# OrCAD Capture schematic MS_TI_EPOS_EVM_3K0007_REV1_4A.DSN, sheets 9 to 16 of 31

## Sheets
9 Pg08: Ethernet RMII: size C
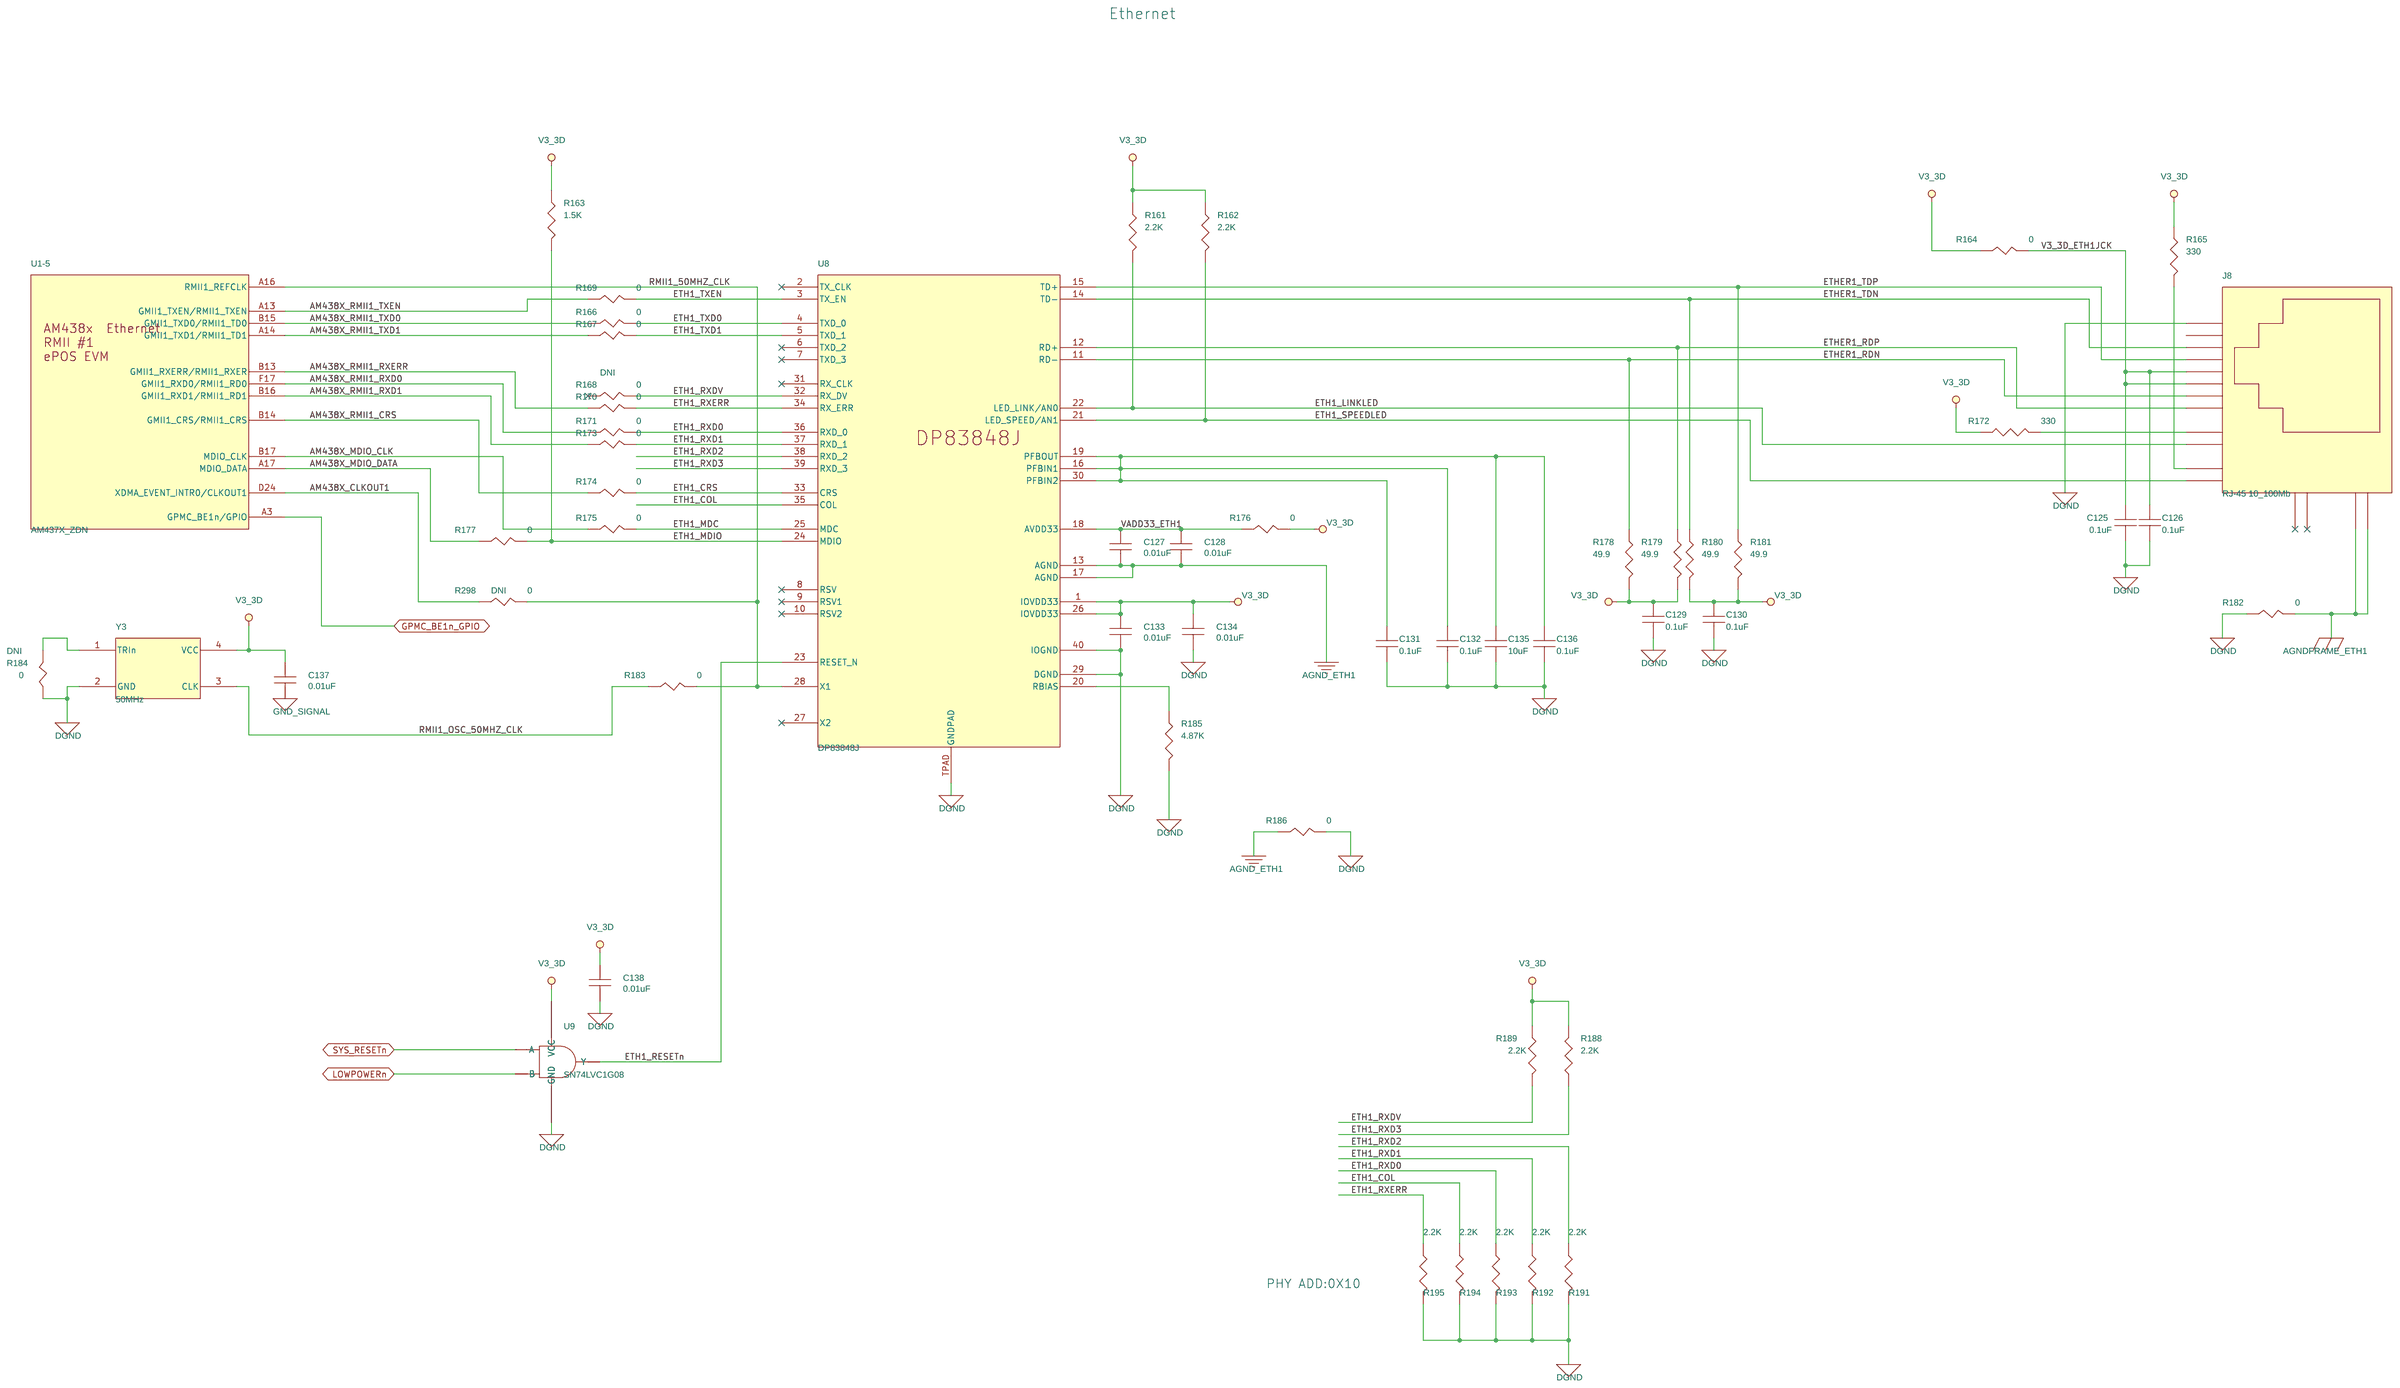
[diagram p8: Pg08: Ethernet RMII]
10 Pg19: USB Port #0: size C
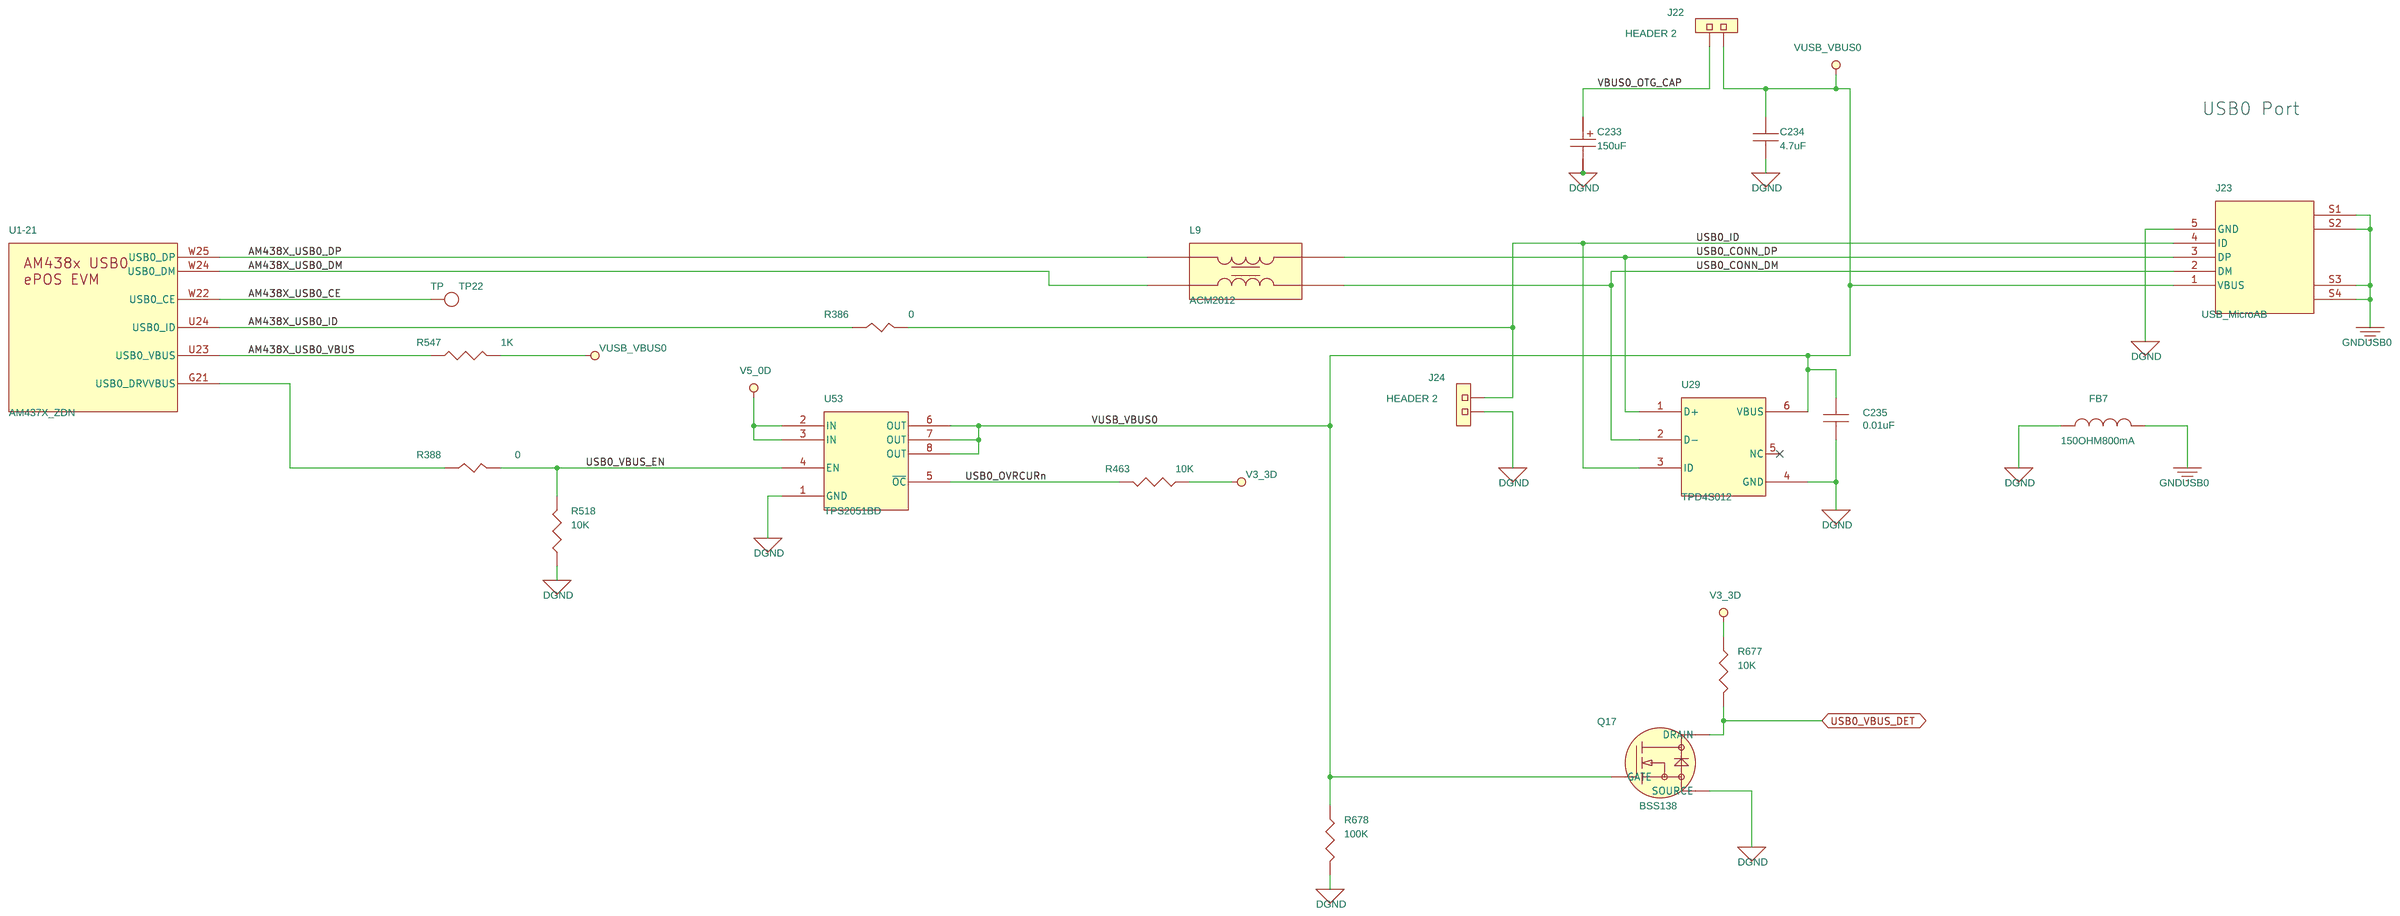
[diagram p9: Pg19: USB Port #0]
11 Pg10: JTAG Debug: size C
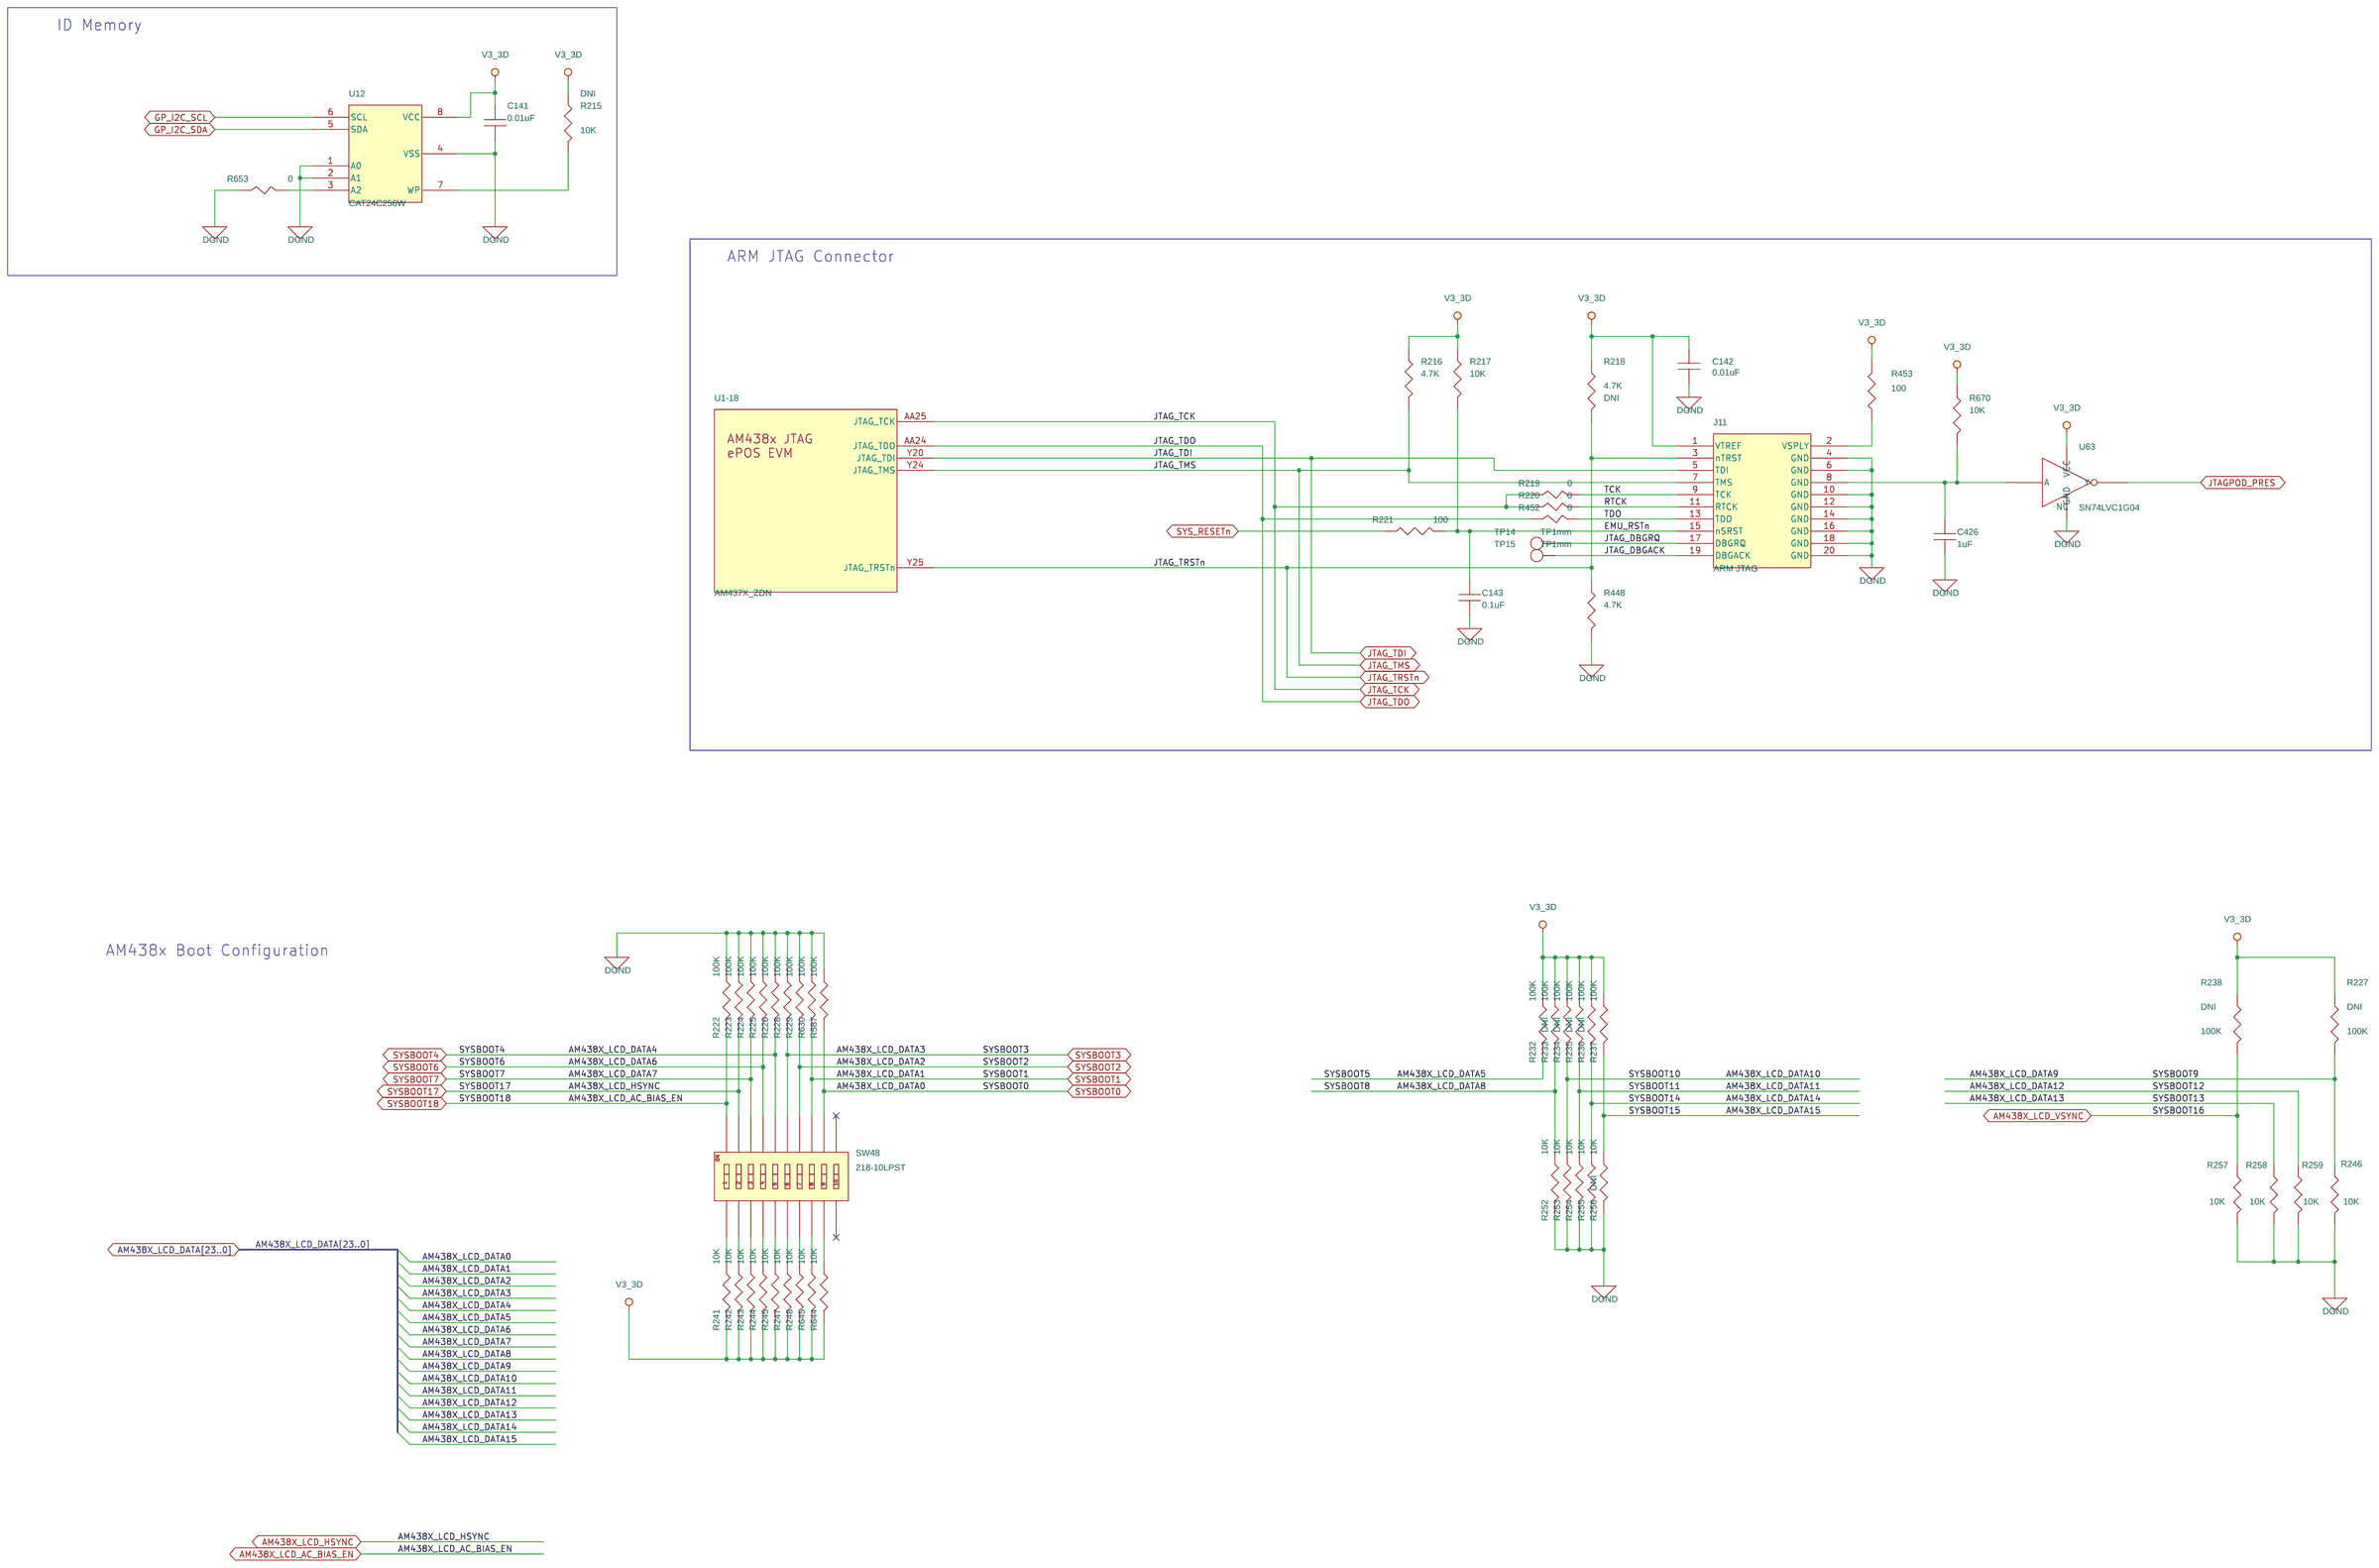
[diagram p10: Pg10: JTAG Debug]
12 Pg01: Title Page
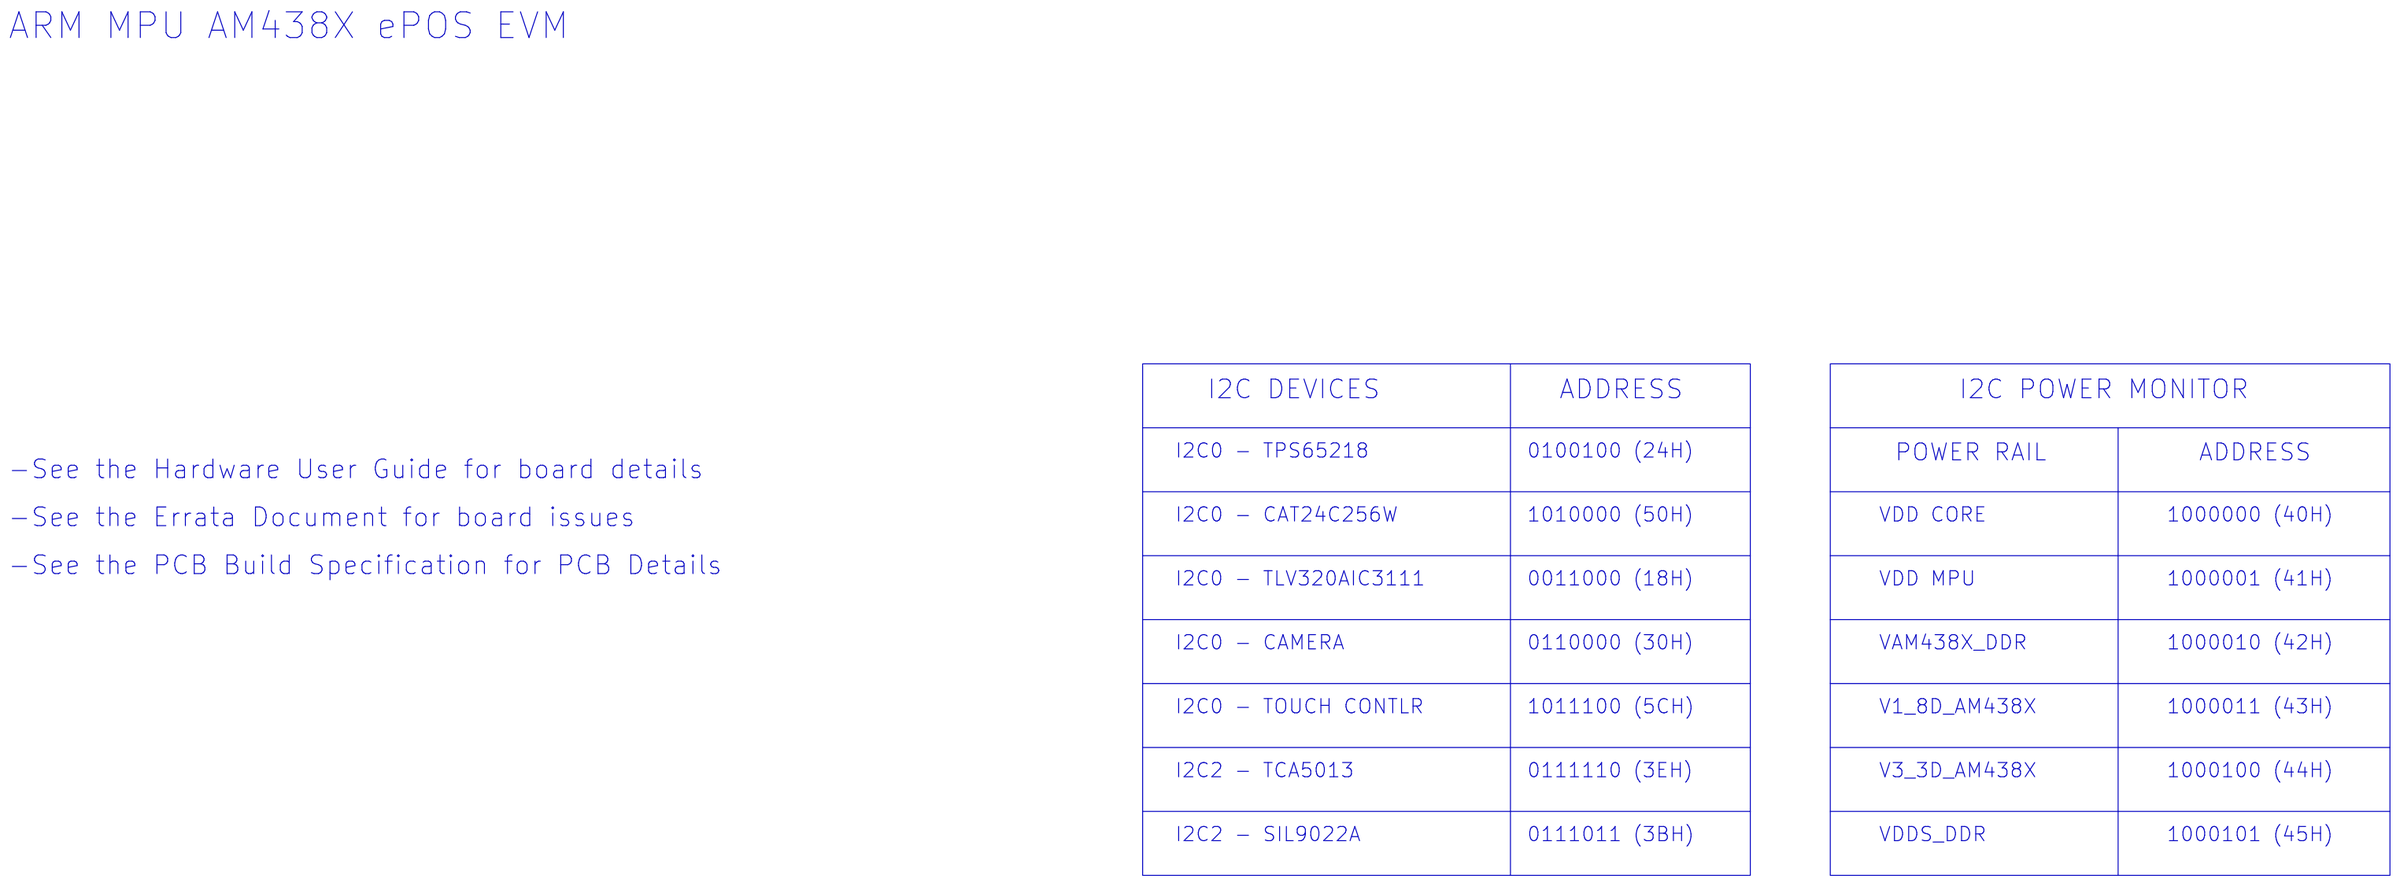
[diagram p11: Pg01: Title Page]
13 Pg21: Smart Card: size C
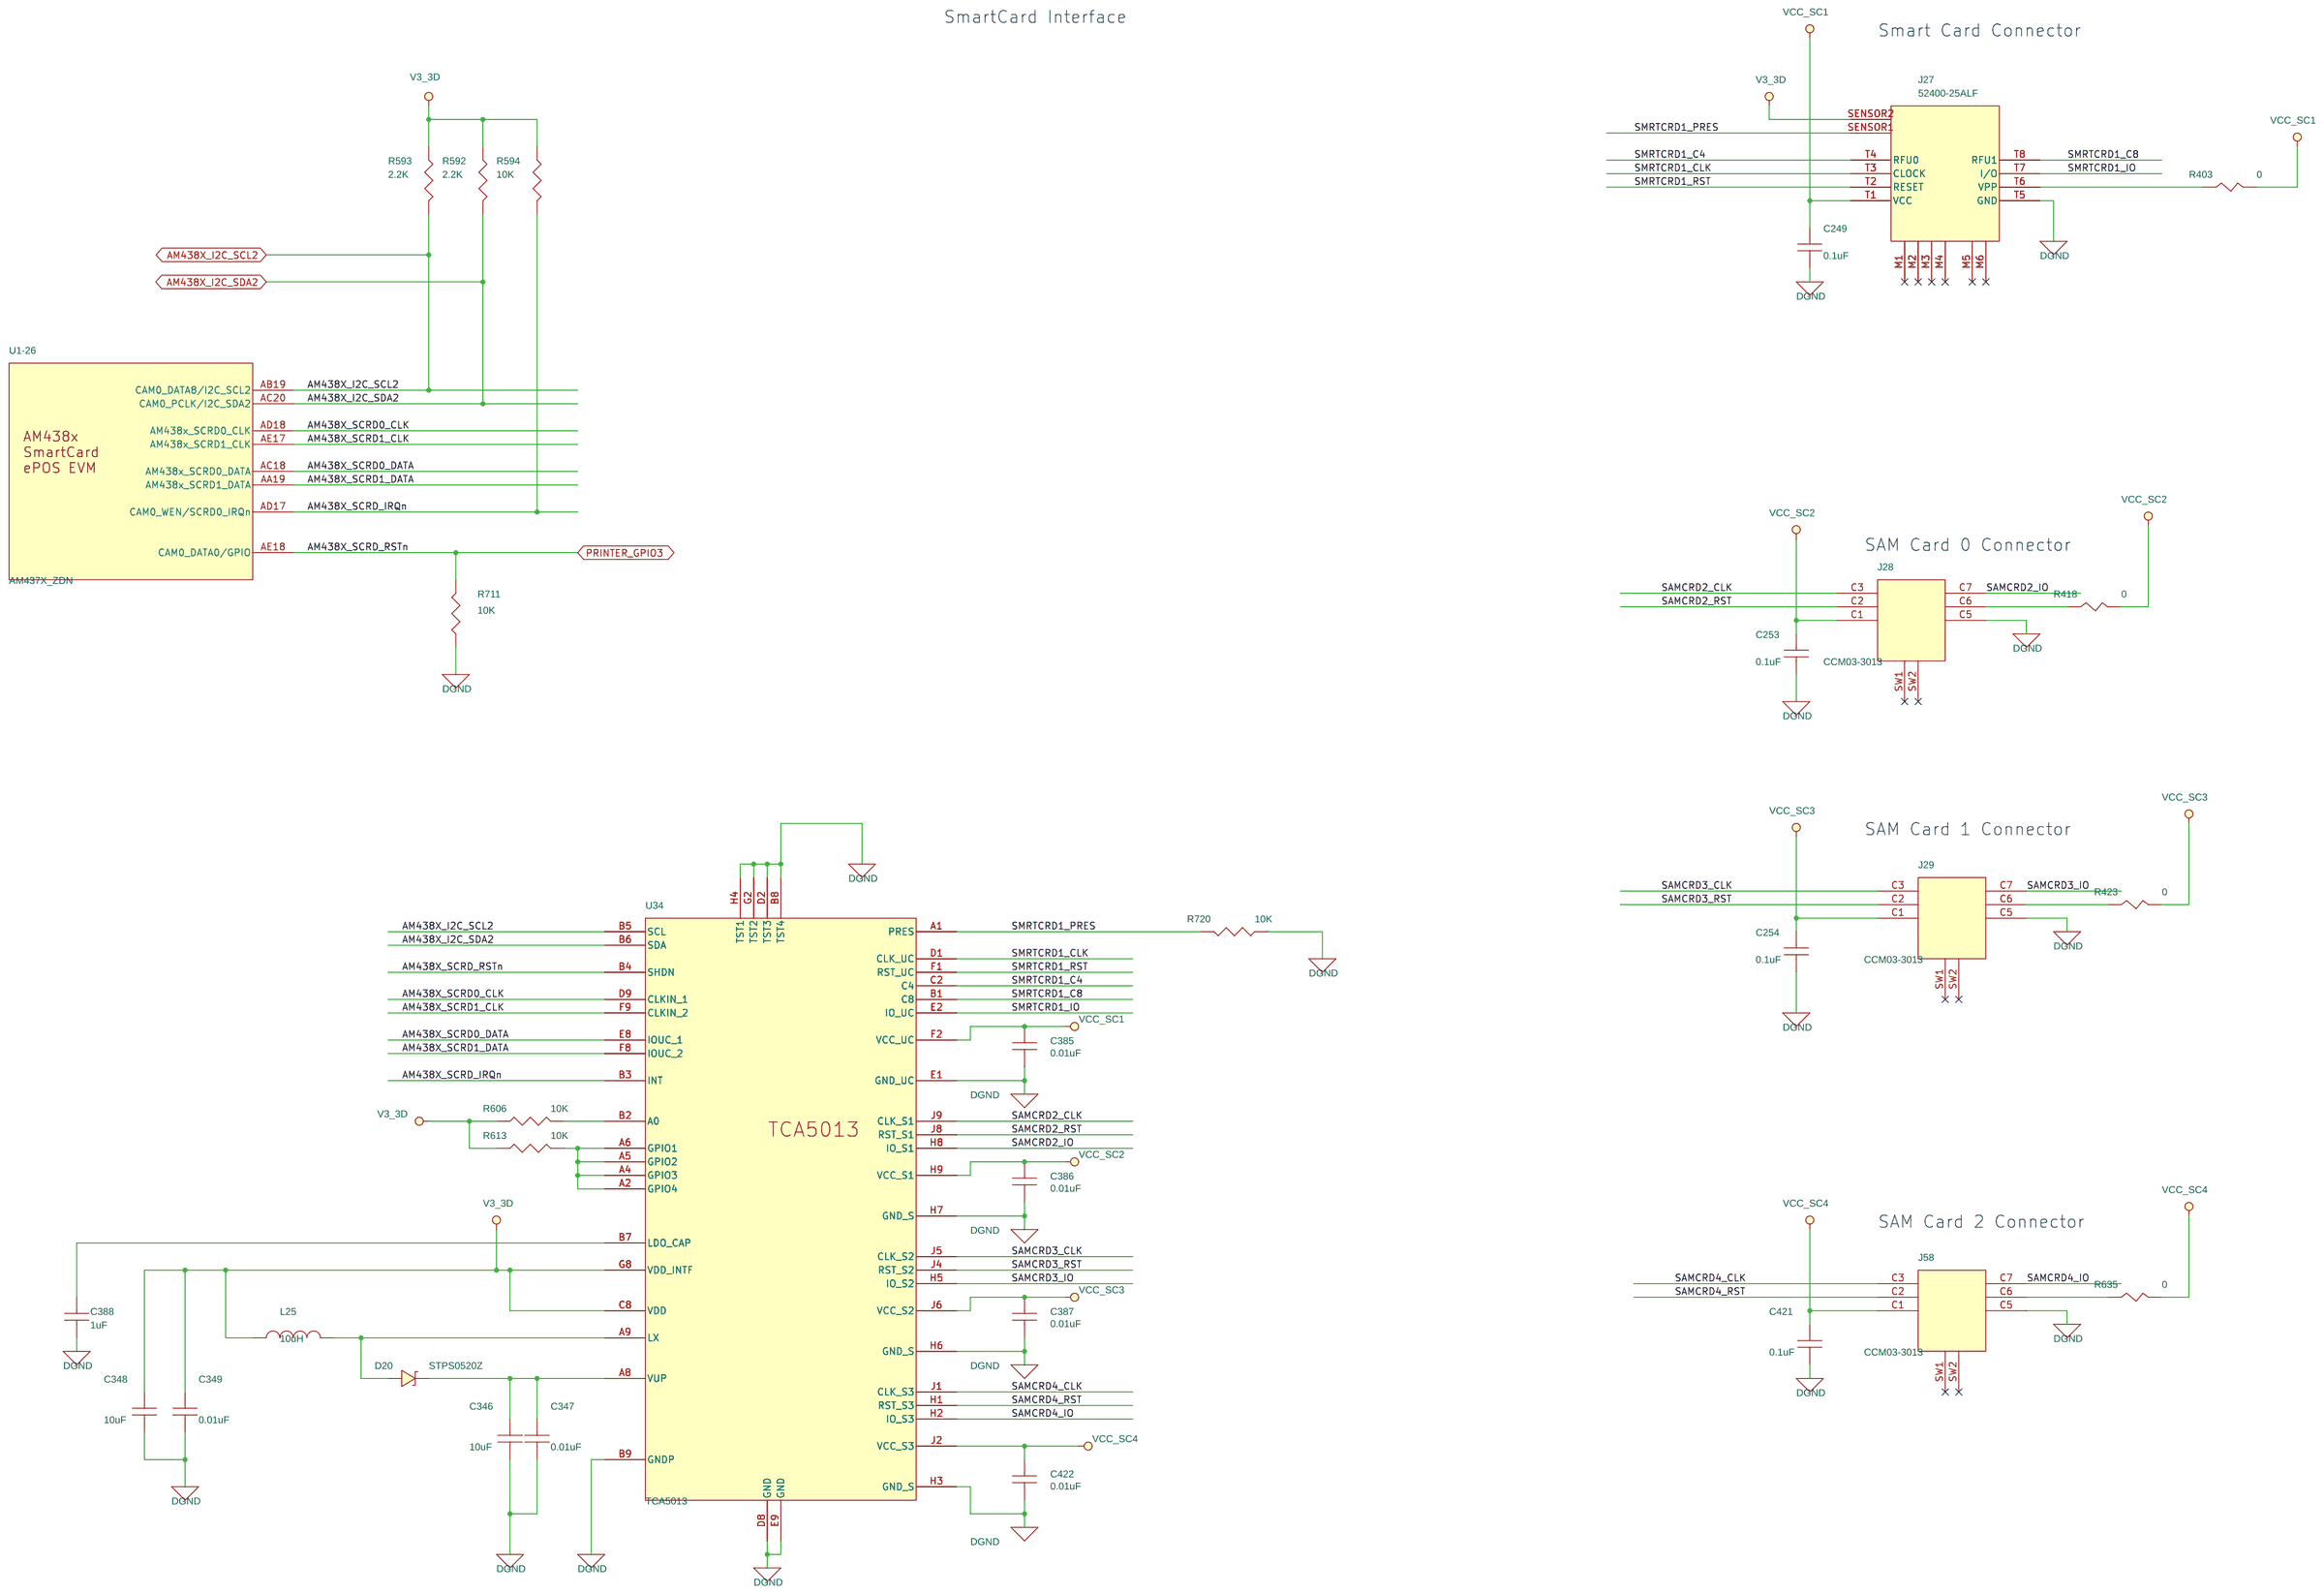
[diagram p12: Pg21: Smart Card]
14 Pg26: Keypad/LED's: size C
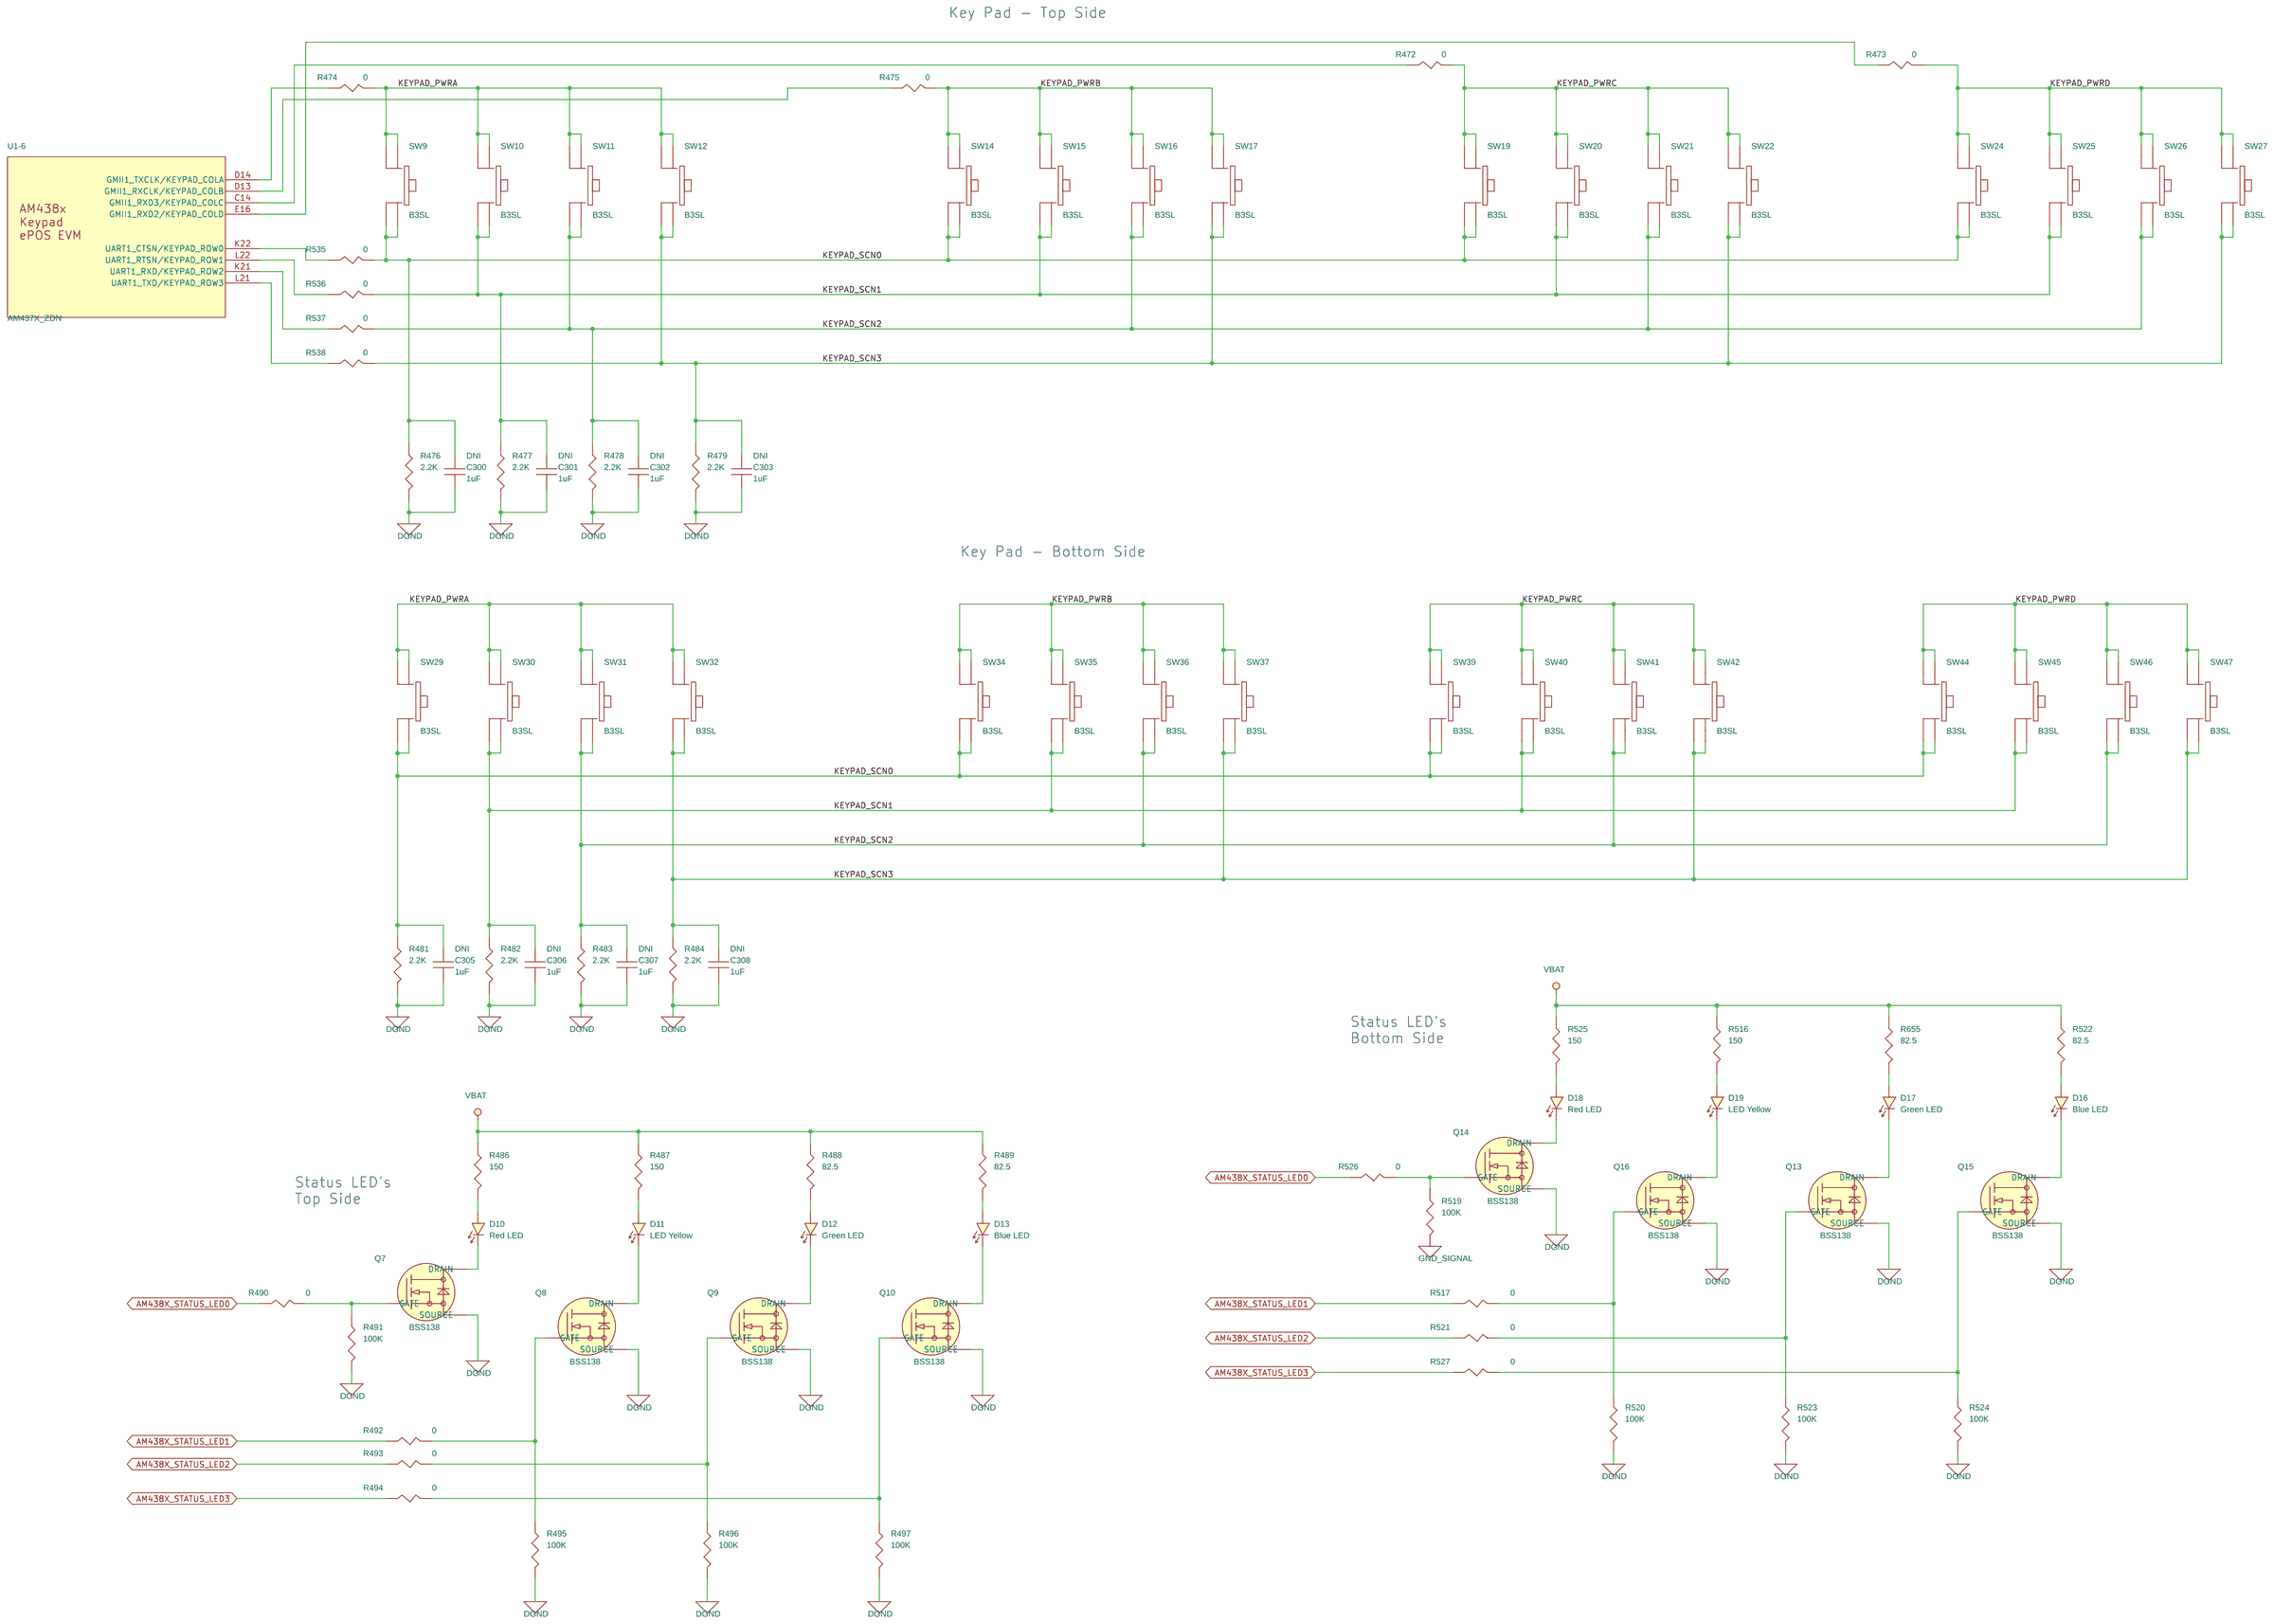
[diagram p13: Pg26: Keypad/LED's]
15 Pg20: USB Port #1: size C
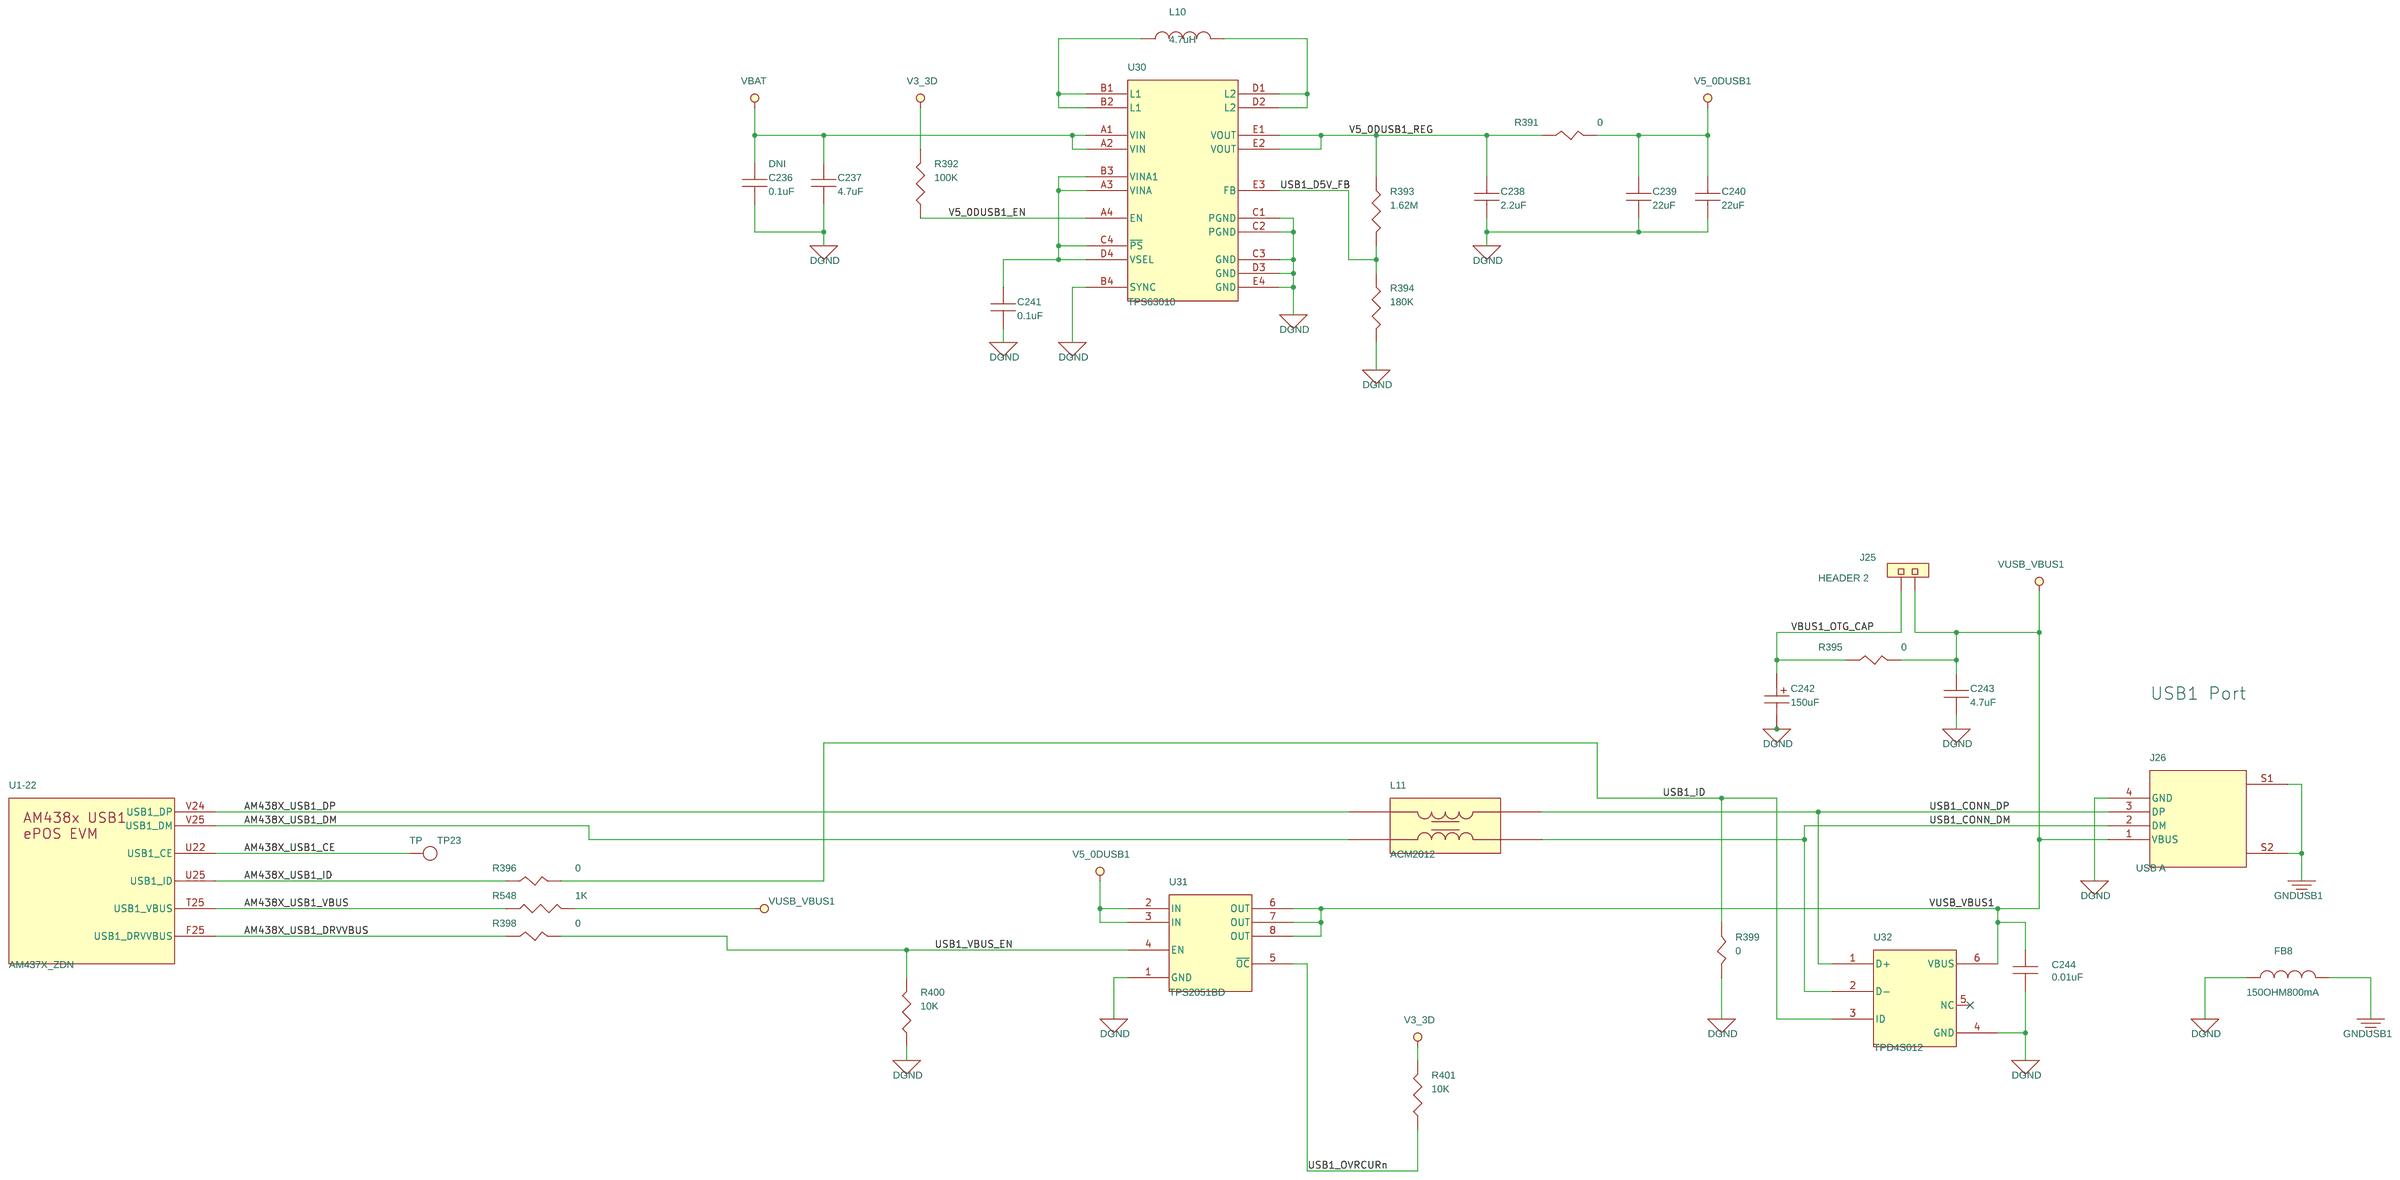
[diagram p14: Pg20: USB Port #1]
16 Pg05: LPDDR2 Memory: size C
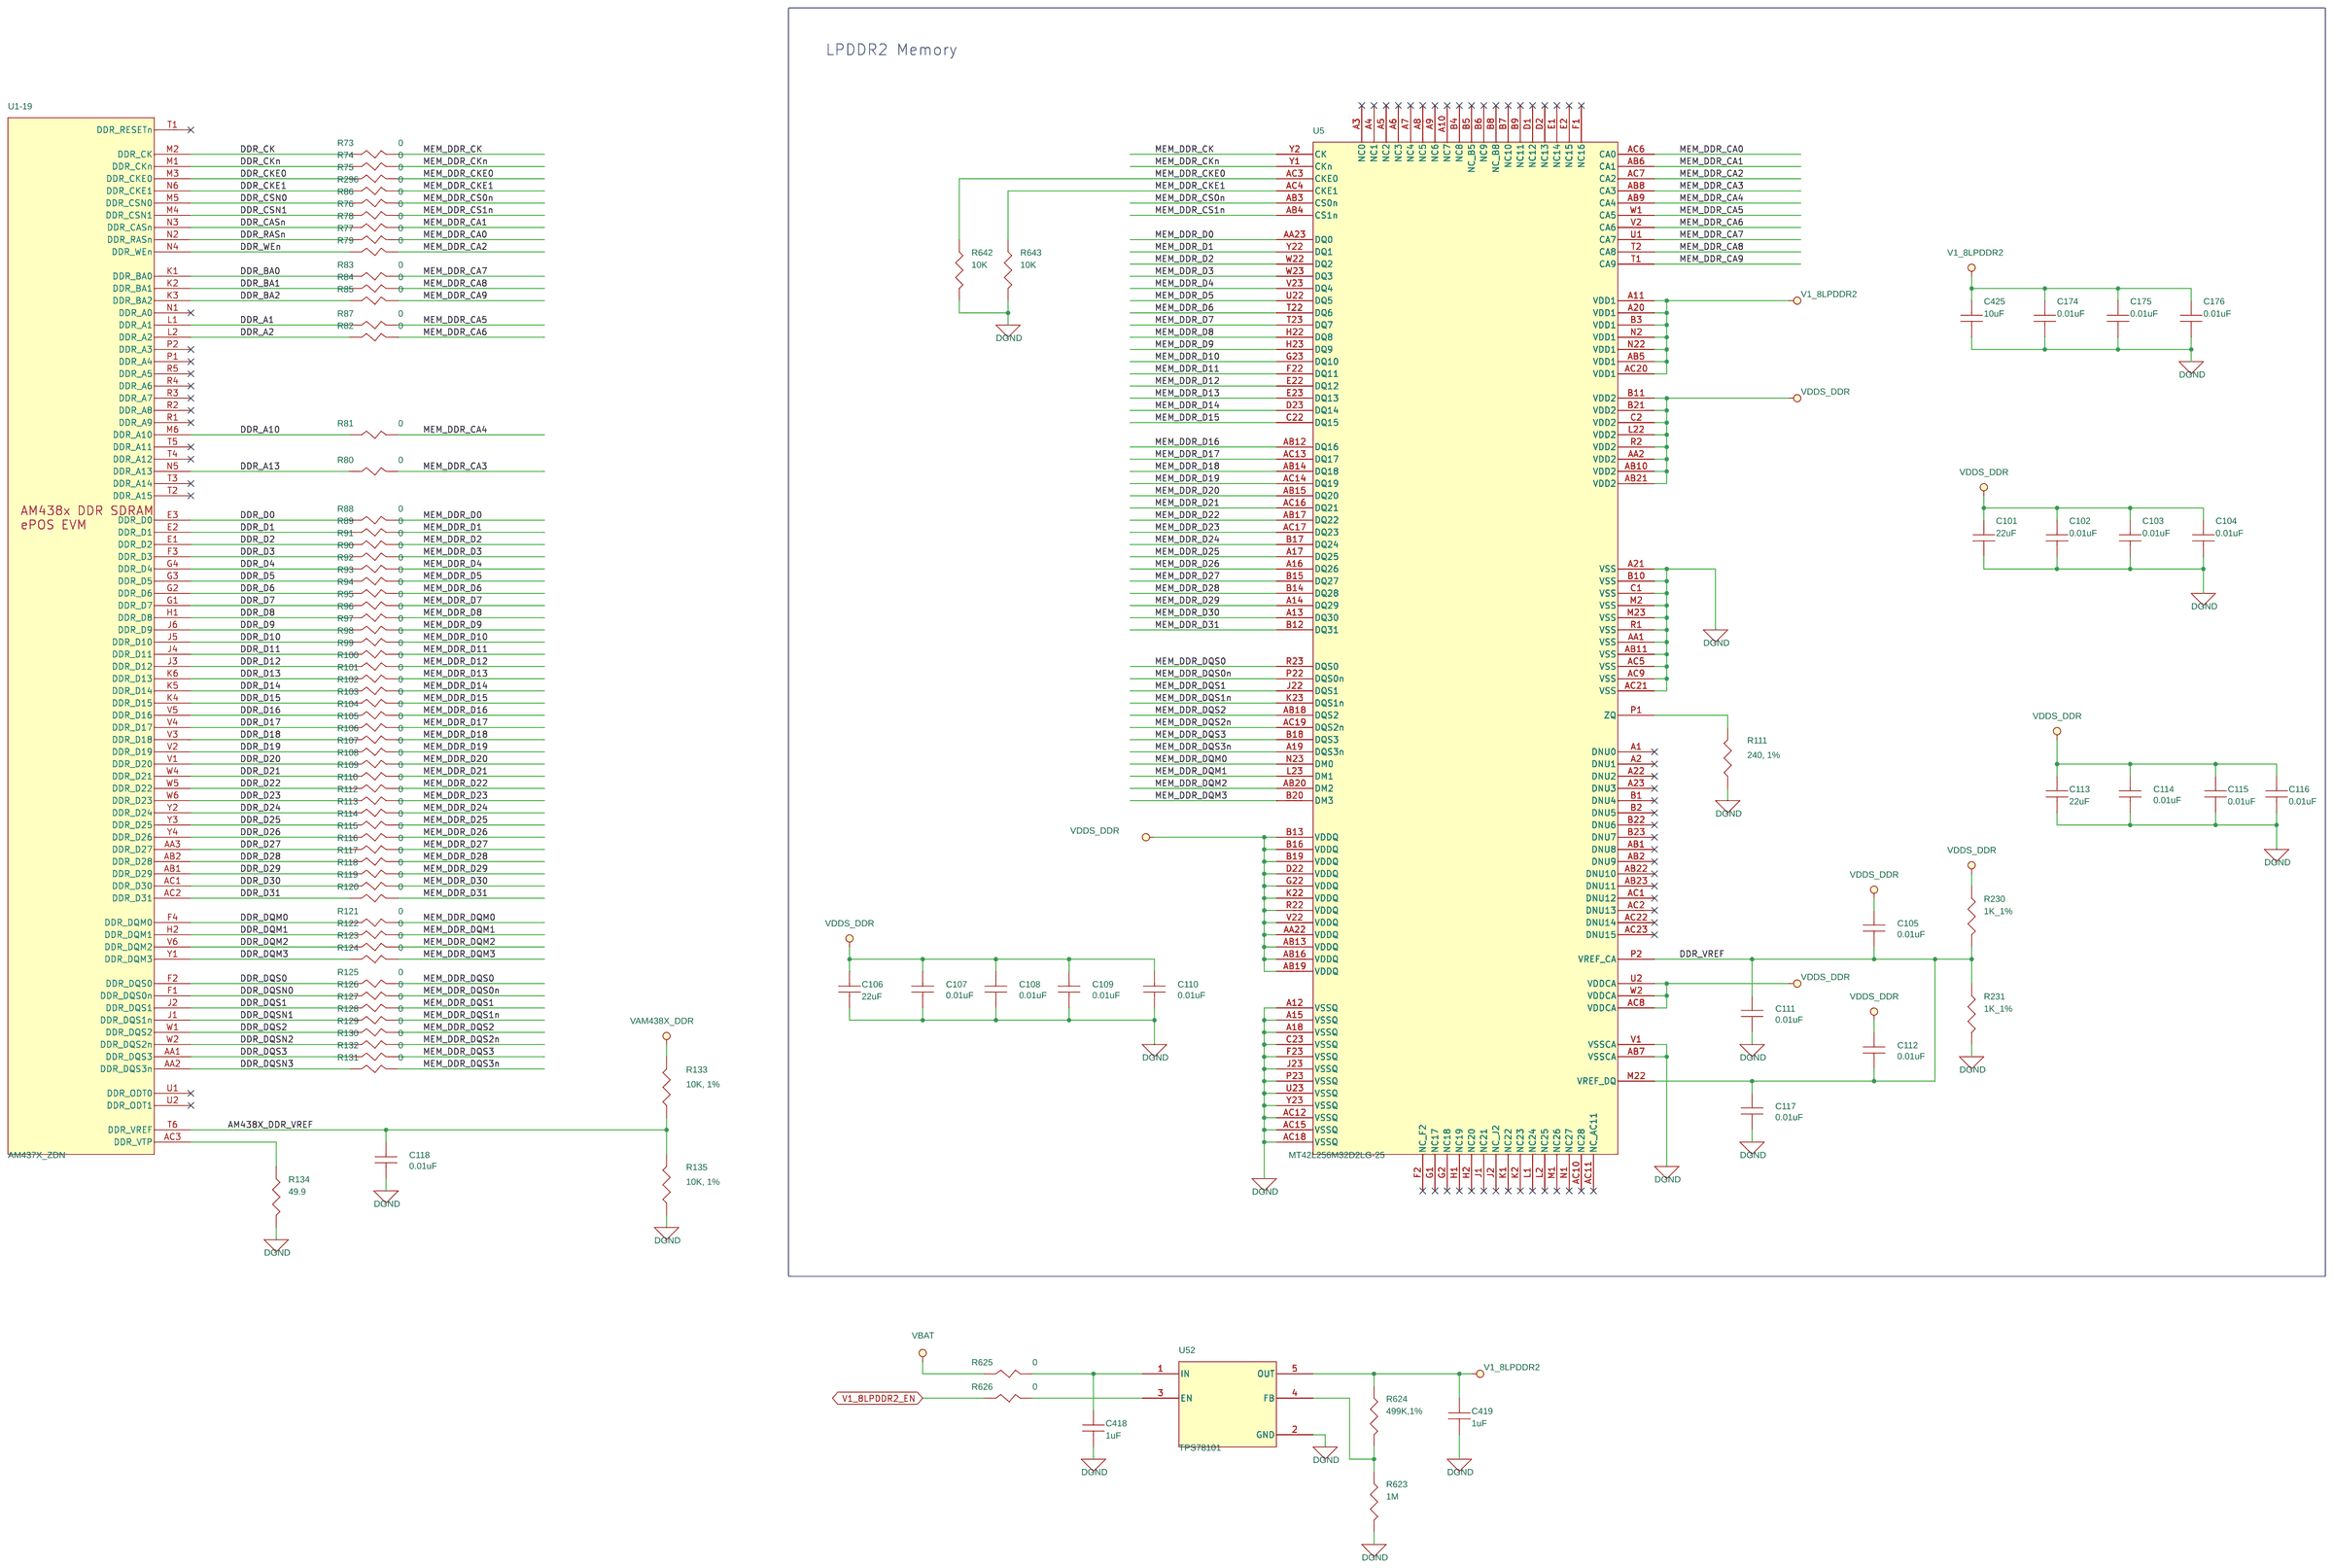
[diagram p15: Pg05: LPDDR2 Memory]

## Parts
sheet Pg05: LPDDR2 Memory
C101  22uF  [SM-7351-CAP-0805]
C102  0.01uF  [SM-7351-CAP-0402]
C103  0.01uF  [SM-7351-CAP-0402]
C104  0.01uF  [SM-7351-CAP-0402]
C105  0.01uF  [SM-7351-CAP-0402]
C106  22uF  [SM-7351-CAP-0805]
C107  0.01uF  [SM-7351-CAP-0402]
C108  0.01uF  [SM-7351-CAP-0402]
C109  0.01uF  [SM-7351-CAP-0402]
C110  0.01uF  [SM-7351-CAP-0402]
C111  0.01uF  [SM-7351-CAP-0402]
C112  0.01uF  [SM-7351-CAP-0402]
C113  22uF  [SM-7351-CAP-0805]
C114  0.01uF  [SM-7351-CAP-0402]
C115  0.01uF  [SM-7351-CAP-0402]
C116  0.01uF  [SM-7351-CAP-0402]
C117  0.01uF  [SM-7351-CAP-0402]
C118  0.01uF  [SM-7351-CAP-0402]
C174  0.01uF  [SM-7351-CAP-0402]
C175  0.01uF  [SM-7351-CAP-0402]
C176  0.01uF  [SM-7351-CAP-0402]
C418  1uF  [SM-7351-CAP-0603]
C419  1uF  [SM-7351-CAP-0603]
C425  10uF  [SM-7351-CAP-0805]
R73  0  [SM-7351-RES-0402]
R74  0  [SM-7351-RES-0402]
R75  0  [SM-7351-RES-0402]
R76  0  [SM-7351-RES-0402]
R77  0  [SM-7351-RES-0402]
R78  0  [SM-7351-RES-0402]
R79  0  [SM-7351-RES-0402]
R80  0  [SM-7351-RES-0402]
R81  0  [SM-7351-RES-0402]
R82  0  [SM-7351-RES-0402]
R83  0  [SM-7351-RES-0402]
R84  0  [SM-7351-RES-0402]
R85  0  [SM-7351-RES-0402]
R86  0  [SM-7351-RES-0402]
R87  0  [SM-7351-RES-0402]
R88  0  [SM-7351-RES-0402]
R89  0  [SM-7351-RES-0402]
R90  0  [SM-7351-RES-0402]
R91  0  [SM-7351-RES-0402]
R92  0  [SM-7351-RES-0402]
R93  0  [SM-7351-RES-0402]
R94  0  [SM-7351-RES-0402]
R95  0  [SM-7351-RES-0402]
R96  0  [SM-7351-RES-0402]
R97  0  [SM-7351-RES-0402]
R98  0  [SM-7351-RES-0402]
R99  0  [SM-7351-RES-0402]
R100  0  [SM-7351-RES-0402]
R101  0  [SM-7351-RES-0402]
R102  0  [SM-7351-RES-0402]
R103  0  [SM-7351-RES-0402]
R104  0  [SM-7351-RES-0402]
R105  0  [SM-7351-RES-0402]
R106  0  [SM-7351-RES-0402]
R107  0  [SM-7351-RES-0402]
R108  0  [SM-7351-RES-0402]
R109  0  [SM-7351-RES-0402]
R110  0  [SM-7351-RES-0402]
R111  240, 1%  [SM-7351-RES-0402]
R112  0  [SM-7351-RES-0402]
R113  0  [SM-7351-RES-0402]
R114  0  [SM-7351-RES-0402]
R115  0  [SM-7351-RES-0402]
R116  0  [SM-7351-RES-0402]
R117  0  [SM-7351-RES-0402]
R118  0  [SM-7351-RES-0402]
R119  0  [SM-7351-RES-0402]
R120  0  [SM-7351-RES-0402]
R121  0  [SM-7351-RES-0402]
R122  0  [SM-7351-RES-0402]
R123  0  [SM-7351-RES-0402]
R124  0  [SM-7351-RES-0402]
R125  0  [SM-7351-RES-0402]
R126  0  [SM-7351-RES-0402]
R127  0  [SM-7351-RES-0402]
R128  0  [SM-7351-RES-0402]
R129  0  [SM-7351-RES-0402]
R130  0  [SM-7351-RES-0402]
R131  0  [SM-7351-RES-0402]
R132  0  [SM-7351-RES-0402]
R133  10K, 1%  [SM-7351-RES-0402]
R134  49.9  [SM-7351-RES-0402]
R135  10K, 1%  [SM-7351-RES-0402]
R230  1K_1%  [SM-7351-RES-0402]
R231  1K_1%  [SM-7351-RES-0402]
R296  0  [SM-7351-RES-0402]
R623  1M  [SM-7351-RES-0402]
R624  499K,1%  [SM-7351-RES-0402]
R625  0  [SM-7351-RES-0402]
R626  0  [SM-7351-RES-0402]
R642  10K  [SM-7351-RES-0402]
R643  10K  [SM-7351-RES-0402]
U5  MT42L256M32D2LG-25  [BGA12X12-168]
U52  TPS78101  [sot23-5-43m]
sheet Pg08: Ethernet RMII
C125  0.1uF  [SM-7351-CAP-0402]
C126  0.1uF  [SM-7351-CAP-0402]
C127  0.01uF  [SM-7351-CAP-0402]
C128  0.01uF  [SM-7351-CAP-0402]
C129  0.1uF  [SM-7351-CAP-0402]
C130  0.1uF  [SM-7351-CAP-0402]
C131  0.1uF  [SM-7351-CAP-0402]
C132  0.1uF  [SM-7351-CAP-0402]
C133  0.01uF  [SM-7351-CAP-0402]
C134  0.01uF  [SM-7351-CAP-0402]
C135  10uF  [SM-7351-CAP-0805]
C136  0.1uF  [SM-7351-CAP-0402]
C137  0.01uF  [SM-7351-CAP-0402]
C138  0.01uF  [SM-7351-CAP-0402]
J8  RJ-45 10_100Mb  [JH2114A82R]
R161  2.2K  [sm-7351-res-0402]
R162  2.2K  [sm-7351-res-0402]
R163  1.5K  [SM-7351-RES-0402]
R164  0  [SM-7351-RES-0603]
R165  330  [SM-7351-RES-0402]
R166  0  [SM-7351-RES-0402]
R167  0  [SM-7351-RES-0402]
R168  0  [SM-7351-RES-0402]
R169  0  [SM-7351-RES-0402]
R170  0  [SM-7351-RES-0402]
R171  0  [SM-7351-RES-0402]
R172  330  [SM-7351-RES-0402]
R173  0  [SM-7351-RES-0402]
R174  0  [SM-7351-RES-0402]
R175  0  [SM-7351-RES-0402]
R176  0  [SM-7351-RES-0603]
R177  0  [SM-7351-RES-0402]
R178  49.9  [SM-7351-RES-0402]
R179  49.9  [SM-7351-RES-0402]
R180  49.9  [SM-7351-RES-0402]
R181  49.9  [SM-7351-RES-0402]
R182  0  [SM-7351-RES-0603]
R183  0  [SM-7351-RES-0402]
R184  0  [SM-7351-RES-0402]
R185  4.87K  [SM-7351-RES-0402]
R186  0  [SM-7351-RES-0603]
R188  2.2K  [sm-7351-res-0402]
R189  2.2K  [sm-7351-res-0402]
R191  2.2K  [sm-7351-res-0402]
R192  2.2K  [sm-7351-res-0402]
R193  2.2K  [sm-7351-res-0402]
R194  2.2K  [sm-7351-res-0402]
R195  2.2K  [sm-7351-res-0402]
R298  0  [SM-7351-RES-0402]
U8  DP83848J  [QFN6X6-40-31M]
U9  SN74LVC1G08  [sm-so-sc70-5]
Y3  50MHz  [osc7x5-71m]
sheet Pg10: JTAG Debug
C141  0.01uF  [SM-7351-CAP-0402]
C142  0.01uF  [SM-7351-CAP-0402]
C143  0.1uF  [SM-7351-CAP-0402]
C426  1uF  [SM-7351-CAP-0603]
J11  ARM JTAG  [hdr2x10-330m]
R215  10K  [SM-7351-RES-0402]
R216  4.7K  [SM-7351-RES-0402]
R217  10K  [SM-7351-RES-0402]
R218  4.7K  [SM-7351-RES-0402]
R219  0  [SM-7351-RES-0402]
R220  0  [SM-7351-RES-0402]
R221  100  [SM-7351-RES-0402]
R222  100K  [SM-7351-RES-0402]
R223  100K  [SM-7351-RES-0402]
R224  100K  [SM-7351-RES-0402]
R225  100K  [SM-7351-RES-0402]
R226  100K  [SM-7351-RES-0402]
R227  100K  [SM-7351-RES-0402]
R228  100K  [SM-7351-RES-0402]
R229  100K  [SM-7351-RES-0402]
R232  100K  [SM-7351-RES-0402]
R233  100K  [SM-7351-RES-0402]
R234  100K  [SM-7351-RES-0402]
R235  100K  [SM-7351-RES-0402]
R236  100K  [SM-7351-RES-0402]
R237  100K  [SM-7351-RES-0402]
R238  100K  [SM-7351-RES-0402]
R241  10K  [SM-7351-RES-0402]
R242  10K  [SM-7351-RES-0402]
R243  10K  [SM-7351-RES-0402]
R244  10K  [SM-7351-RES-0402]
R245  10K  [SM-7351-RES-0402]
R246  10K  [SM-7351-RES-0402]
R247  10K  [SM-7351-RES-0402]
R248  10K  [SM-7351-RES-0402]
R252  10K  [SM-7351-RES-0402]
R253  10K  [SM-7351-RES-0402]
R254  10K  [SM-7351-RES-0402]
R255  10K  [SM-7351-RES-0402]
R256  10K  [SM-7351-RES-0402]
R257  10K  [SM-7351-RES-0402]
R258  10K  [SM-7351-RES-0402]
R259  10K  [SM-7351-RES-0402]
R448  4.7K  [SM-7351-RES-0402]
R452  0  [SM-7351-RES-0402]
R453  100  [SM-7351-RES-0402]
R587  100K  [SM-7351-RES-0402]
R630  100K  [SM-7351-RES-0402]
R644  10K  [SM-7351-RES-0402]
R645  10K  [SM-7351-RES-0402]
R653  0  [SM-7351-RES-0402]
R670  10K  [SM-7351-RES-0402]
SW48  218-10LPST  [SW10_50_550X230_SMD]
TP14  TP1mm  [tp_smd1mmcircle]
TP15  TP1mm  [tp_smd1mmcircle]
U12  CAT24C256W  [SOIC8_MC]
U63  SN74LVC1G04  [SC70-5-43M]
sheet Pg19: USB Port #0
C233  150uF  [SM-7351-CAP-2917]
C234  4.7uF  [SM-7351-CAP-0603]
C235  0.01uF  [SM-7351-CAP-0402]
FB7  150OHM800mA  [sm-7351-ind-0805]
J22  HEADER 2  [header_2x1]
J23  USB_MicroAB  [ZX62-AB-5PA]
J24  HEADER 2  [header_2x1]
L9  ACM2012  [ACM2012H]
Q17  BSS138  [SOT23-3]
R386  0  [SM-7351-RES-0402]
R388  0  [SM-7351-RES-0402]
R463  10K  [SM-7351-RES-0402]
R518  10K  [SM-7351-RES-0402]
R547  1K  [SM-7351-RES-0402]
R677  10K  [SM-7351-RES-0402]
R678  100K  [SM-7351-RES-0402]
TP22  TP  [TH_TP_5002]
U29  TPD4S012  [U_6_DRY]
U53  TPS2051BD  [U_8_D]
sheet Pg20: USB Port #1
C236  0.1uF  [SM-7351-CAP-0402]
C237  4.7uF  [SM-7351-CAP-0603]
C238  2.2uF  [SM-7351-CAP-0402]
C239  22uF  [SM-7351-CAP-0805]
C240  22uF  [SM-7351-CAP-0805]
C241  0.1uF  [SM-7351-CAP-0402]
C242  150uF  [SM-7351-CAP-2917]
C243  4.7uF  [SM-7351-CAP-0603]
C244  0.01uF  [SM-7351-CAP-0402]
FB8  150OHM800mA  [sm-7351-ind-0805]
J25  HEADER 2  [header_2x1]
J26  USB A  [usb_std_a_th]
L10  4.7uH  [smd_slf7055t]
L11  ACM2012  [ACM2012H]
R391  0  [SM-7351-RES-0603]
R392  100K  [SM-7351-RES-0402]
R393  1.62M  [SM-7351-RES-0402]
R394  180K  [SM-7351-RES-0402]
R395  0  [SM-7351-RES-0603]
R396  0  [SM-7351-RES-0402]
R398  0  [SM-7351-RES-0402]
R399  0  [SM-7351-RES-0402]
R400  10K  [SM-7351-RES-0402]
R401  10K  [SM-7351-RES-0402]
R548  1K  [SM-7351-RES-0402]
TP23  TP  [TH_TP_5002]
U30  TPS63010  [u_20_dsbga]
U31  TPS2051BD  [U_8_D]
U32  TPD4S012  [U_6_DRY]
sheet Pg21: Smart Card
C249  0.1uF  [SM-7351-CAP-0402]
C253  0.1uF  [SM-7351-CAP-0402]
C254  0.1uF  [SM-7351-CAP-0402]
C346  10uF  [SM-7351-CAP-0805]
C347  0.01uF  [SM-7351-CAP-0402]
C348  10uF  [SM-7351-CAP-0805]
C349  0.01uF  [SM-7351-CAP-0402]
C385  0.01uF  [SM-7351-CAP-0402]
C386  0.01uF  [SM-7351-CAP-0402]
C387  0.01uF  [SM-7351-CAP-0402]
C388  1uF  [SM-7351-CAP-0603]
C421  0.1uF  [SM-7351-CAP-0402]
C422  0.01uF  [SM-7351-CAP-0402]
D20  STPS0520Z  [sod-123]
J27  52400-25ALF  [TH_CON_52400-25ALF]
J28  CCM03-3013  [CN-SIM-CCM03]
J29  CCM03-3013  [CN-SIM-CCM03]
J58  CCM03-3013  [CN-SIM-CCM03]
L25  10uH  [ind-mlz2012-57m]
R403  0  [SM-7351-RES-0402]
R418  0  [SM-7351-RES-0402]
R423  0  [SM-7351-RES-0402]
R592  2.2K  [sm-7351-res-0402]
R593  2.2K  [sm-7351-res-0402]
R594  10K  [SM-7351-RES-0402]
R606  10K  [SM-7351-RES-0402]
R613  10K  [SM-7351-RES-0402]
R635  0  [SM-7351-RES-0402]
R711  10K  [SM-7351-RES-0402]
R720  10K  [SM-7351-RES-0402]
U34  TCA5013  [bga5x5-48-47m]
sheet Pg26: Keypad/LED's
C300  1uF  [SM-7351-CAP-0402]
C301  1uF  [SM-7351-CAP-0402]
C302  1uF  [SM-7351-CAP-0402]
C303  1uF  [SM-7351-CAP-0402]
C305  1uF  [SM-7351-CAP-0402]
C306  1uF  [SM-7351-CAP-0402]
C307  1uF  [SM-7351-CAP-0402]
C308  1uF  [SM-7351-CAP-0402]
D10  Red LED  [sm_led_0805]
D11  LED Yellow  [LEDLTST-S220]
D12  Green LED  [sm_led_0805]
D13  Blue LED  [sm_led_0805]
D16  Blue LED  [sm_led_0805]
D17  Green LED  [sm_led_0805]
D18  Red LED  [sm_led_0805]
D19  LED Yellow  [LEDLTST-S220]
Q7  BSS138  [SOT23-3]
Q8  BSS138  [SOT23-3]
Q9  BSS138  [SOT23-3]
Q10  BSS138  [SOT23-3]
Q13  BSS138  [SOT23-3]
Q14  BSS138  [SOT23-3]
Q15  BSS138  [SOT23-3]
Q16  BSS138  [SOT23-3]
R472  0  [SM-7351-RES-0402]
R473  0  [SM-7351-RES-0402]
R474  0  [SM-7351-RES-0402]
R475  0  [SM-7351-RES-0402]
R476  2.2K  [sm-7351-res-0402]
R477  2.2K  [sm-7351-res-0402]
R478  2.2K  [sm-7351-res-0402]
R479  2.2K  [sm-7351-res-0402]
R481  2.2K  [sm-7351-res-0402]
R482  2.2K  [sm-7351-res-0402]
R483  2.2K  [sm-7351-res-0402]
R484  2.2K  [sm-7351-res-0402]
R486  150  [SM-7351-RES-0402]
R487  150  [SM-7351-RES-0402]
R488  82.5  [sm-7351-res-0402]
R489  82.5  [sm-7351-res-0402]
R490  0  [SM-7351-RES-0402]
R491  100K  [SM-7351-RES-0402]
R492  0  [SM-7351-RES-0402]
R493  0  [SM-7351-RES-0402]
R494  0  [SM-7351-RES-0402]
R495  100K  [SM-7351-RES-0402]
R496  100K  [SM-7351-RES-0402]
R497  100K  [SM-7351-RES-0402]
R516  150  [SM-7351-RES-0402]
R517  0  [SM-7351-RES-0402]
R519  100K  [SM-7351-RES-0402]
R520  100K  [SM-7351-RES-0402]
R521  0  [SM-7351-RES-0402]
R522  82.5  [sm-7351-res-0402]
R523  100K  [SM-7351-RES-0402]
R524  100K  [SM-7351-RES-0402]
R525  150  [SM-7351-RES-0402]
R526  0  [SM-7351-RES-0402]
R527  0  [SM-7351-RES-0402]
R535  0  [SM-7351-RES-0402]
R536  0  [SM-7351-RES-0402]
R537  0  [SM-7351-RES-0402]
R538  0  [SM-7351-RES-0402]
R655  82.5  [sm-7351-res-0402]
SW9  B3SL  [SW_B3SL-1022P]
SW10  B3SL  [SW_B3SL-1022P]
SW11  B3SL  [SW_B3SL-1022P]
SW12  B3SL  [SW_B3SL-1022P]
SW14  B3SL  [SW_B3SL-1022P]
SW15  B3SL  [SW_B3SL-1022P]
SW16  B3SL  [SW_B3SL-1022P]
SW17  B3SL  [SW_B3SL-1022P]
SW19  B3SL  [SW_B3SL-1022P]
SW20  B3SL  [SW_B3SL-1022P]
SW21  B3SL  [SW_B3SL-1022P]
SW22  B3SL  [SW_B3SL-1022P]
SW24  B3SL  [SW_B3SL-1022P]
SW25  B3SL  [SW_B3SL-1022P]
SW26  B3SL  [SW_B3SL-1022P]
SW27  B3SL  [SW_B3SL-1022P]
SW29  B3SL  [SW_B3SL-1022P]
SW30  B3SL  [SW_B3SL-1022P]
SW31  B3SL  [SW_B3SL-1022P]
SW32  B3SL  [SW_B3SL-1022P]
SW34  B3SL  [SW_B3SL-1022P]
SW35  B3SL  [SW_B3SL-1022P]
SW36  B3SL  [SW_B3SL-1022P]
SW37  B3SL  [SW_B3SL-1022P]
SW39  B3SL  [SW_B3SL-1022P]
SW40  B3SL  [SW_B3SL-1022P]
SW41  B3SL  [SW_B3SL-1022P]
SW42  B3SL  [SW_B3SL-1022P]
SW44  B3SL  [SW_B3SL-1022P]
SW45  B3SL  [SW_B3SL-1022P]
SW46  B3SL  [SW_B3SL-1022P]
SW47  B3SL  [SW_B3SL-1022P]
U1  AM437X_ZDN  [AM437X_ZDN]  (sections -1,-10,-11,-12,-13,-14,-15,-16,-17,-18,-19,-2,-20,-21,-22,-23,-24,-25,-26,-27,-3,-4,-5,-6,-7,-8,-9)

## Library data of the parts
C101 C106 C113 C239 C240 = 1C_22uFCapacitor16V10%0805: Mistral Part No: 120014060009-R
C102-C105 C107-C112 C114-C118 C127 C128 C133 C134 C137 C138 C141 C142 C174-C176 C235 C244 C347 C349 C385-C387 C422 = 1C_0.01uFCapacitor16V10%0402: Cost100: 0; Cost10K: 0.01; Mistral Part No: 120009030032-R
C388 C418 C419 C426 = 1C_1uFCapacitor50V10%0603: Cost10K: 0.04; Mistral Part No: M120016080002
C135 C346 C348 C425 = 1C_10uFCapacitor16V10%0805: Cost10K: 0.04; Mistral Part No: 120011040011-R
R73-R110 R112-R132 R166 R167 R169-R171 R173-R175 R177 R183 R219 R220 R296 R386 R388 R396 R398 R399 R403 R418 R423 R452 R472-R475 R490 R492-R494 R517 R521 R526 R527 R535-R538 R625 R626 R635 R653 = 1R_ZeroOhmResistor1_16W0402: Mistral Part No: 110014100008-R
R111 = 1R_240OhmResistor1_10W1%0402: Cost10K: 0; Mistral Part No: 110011060017-R
R133 R135 = 1R_10KOhmResistor1_10W1%0402: Cost100: 0.01; Cost10K: 0; Mistral Part No: 110015050015-R
R134 R178-R181 = 1R_49.9OhmResistor1_16W0402: Cost100: 0.06; Cost10K: 0.06; Mistral Part No: 110014060026-R
R230 R231 = 1R_2.2KohmResistor1_8W1%0402: RES SMD 1K OHM 1% 1/10W 0402; Cost10K: 0; DescriptiveText: RES SMD 1K OHM 1% 1/10W 0402; Mfr: Panasonic Electronic Components; MfrNum: ERJ-2RKF1001X; Mistral Part No: 110009030411-R; Part Number: RES SMD 1K OHM 1% 1/10W 0402; PartName: RES SMD 1K OHM 1% 1/10W 0402
R623 = 1R_1MOhmResistor1_16W0402: Cost100: 0.01; Cost10K: 0; Mistral Part No: 110014060045-R
R624 = 1R_499Kohm1_16W1%smd0402: Cost100: 0; Cost10K: 0.02; Mistral Part No: 110009090015-P
R217 R246 R252-R255 R257-R259 R400 R401 R463 R518 R594 R606 R613 R642 R643 R670 R677 R711 R720 = 1R_10KOhmResistor1_16W0402: Cost10K: 0; Mistral Part No: 110011060003-R
U5 = 1A_MT42L256M32D2LG: Mistral Part No: M141116080001
U52 = 1A_TPS78101: MfrNum: TPS78101DDCR; Mistral Part No: 142014060013-R
C125 C126 C129-C132 C136 C143 C241 C249 C253 C254 C421 = 1C_0.1uFCapacitor16V10%0402: Cost10K: 0.01; MfrNum: C0402C104K4RACTU; Mistral Part No: 120009030060-R
J8 = 2J_ConnectorRJ45_10_100Mb: Cost100: 3; Mistral Part No: M150016080002
R161 R162 R188 R189 R191-R195 R476-R479 R481-R484 R592 R593 = 1R_2.2KOhmResistor1_16W0402: Cost100: 0.05; Cost10K: 0; Mistral Part No: 110014060053-R
R163 = 1R_1.5KohmResistor1_16W5%0402: Cost100: 0; Cost10K: 0.02; MfrNum: RMCF0402JT1K50; Mistral Part No: 110014060038-R
R164 R176 R182 R186 R391 R395 = 1R_ZeroOhmResistor1_16W0603: Cost10K: 0.05; Mistral Part No: 110014070017-R
R165 R172 = 1R_330ohm1_16W5%smd0402: Cost100: 0; Cost10K: 0.02; Mistral Part No: 110009030684-R
R168 R184 R298 = 1R_ZeroOhmResistor1_16W0402: Loading: DNI; Mistral Part No: 110014100008-R
R185 = 1R_4.87Kohm1_16W1%smd0402: Cost100: 0; Cost10K: 0.02; Mistral Part No: M110016080003
U8 = 1A_DP83848J: Mistral Part No: M141016080001
U9 = SN74LVC1G08DCKT_SC70: MfrNum: SN74LVC1G08DCKR; Mistral Part No: 141009030227
Y3 = 1Y_Oscillator50MHzSMD: MfrNum: ASV-50.000MHZ-EJ-T; Mistral Part No: M130016080009
J11 = 2H_Header10x2_ARMJTAG: Cost100: 1.2; Mistral Part No: 150014050024-R
R215 R256 = 1R_10KOhmResistor1_16W0402: Cost10K: 0; Loading: DNI; Mistral Part No: 110011060003-R
R216 R448 = 1R_4.7KOhmResistor1_16W0402: Cost100: 0; Cost10K: 0.02; Mistral Part No: 110014060028-R
R218 = 1R_4.7KOhmResistor1_16W0402: Cost100: 0; Cost10K: 0.02; Loading: DNI; Mistral Part No: 110014060028-R
R221 R453 = 1R_100ohm1_16W1%SMD0402: Cost100: 0.01; Cost10K: 0; Mistral Part No: 110014060039-R
R222-R226 R228 R229 R587 R630 = 1R_10KOhmResistor1_16W0402: Cost100: 0.01; Cost10K: 0; DescriptiveText: Resistor 100Kohm 1/16W 1% 0402; Mfr: Stackpole Electronics; MfrNum: RMCF0402FT100K; Mistral Part No: 110014060043-R; PartName: 100Kohm1/16W1%SMD0402; TIIntPartnumber: 1R0181
R227 R233-R236 R238 = 1R_100KOhmResistor1_16W0402: Cost100: 0.01; Cost10K: 0; Loading: DNI; Mistral Part No: 110014060043-R
R232 R237 R392 R491 R495-R497 R519 R520 R523 R524 R678 = 1R_100KOhmResistor1_16W0402: Cost100: 0.01; Cost10K: 0; Mistral Part No: 110014060043-R
R241-R245 R247 R248 R644 R645 = 1R_100KOhmResistor1_16W0402: Cost100: 0.03; Cost10K: 0; DescriptiveText: Resistor 10Kohm 1/16W 5% 0402; Mfr: Rohm; MfrNum: MCR01MZPJ103; Mistral Part No: 110011060003-R; PartName: 10Kohm1/16W5%SMD0402; TIIntPartnumber: 1R0168
SW48 = SW10_218-10LPST: SWITCH DIP SPST HALF PITCH 10POS SMD; Chkd/date: VASANTHA/250816; Crtd /date: VASANTHA/250816; Custom_Duty: 24%; Customs_HS_Code: 85369090; DescriptiveText: SWITCH DIP SPST HALF PITCH 10POS SMD; Distributor_name: DIGIKEY; Distributor_part_number: CT21810LPST-ND; Mfr: CTS; Mfr_name: CTS; Mistral Part No: 130016080032-R; Package: SMD; Part_type: ELECTRO-MECHANICAL\SWITCH; Project: EPOS_EVM; RoHS: RoHS; Temperature: -55°C+85°C; Tolerance: NA; Voltage: NA; Wattage: NA; Weight: NA; Datasheet: Y:\MIS_DATABASE\DATASHEETS\MISC\SWITCHES\128-12LPST.PDF
TP14 TP15 = 2H_Testpoint_SMD1mmCircle
U12 = 1A_CAT24C256W: Mistral Part No: 141110050004-R
U63 = 1A_SN74LVC1G04: Cost10K: 0.23; MfrNum: SN74LVC1G04DCKR; Mistral Part No: 141009070007-R
C233 C242 = 1C_150uFCapacitor10V10%2917: DescriptiveText: 150µF ±10% Molded Tantalum Capacitors 10V 2917 (7343 Metric) 100 mOhm; MfrNum: T495D157K010ATE100; Mistral Part No: 120014060014-R
C234 C237 C243 = 1C_4.7uFCapacitor16V10%0603: Cost100: 0.01; Cost10K: 0; Mistral Part No: 120011050004-R
FB7 FB8 = 1L_FerBead_180ohm200mA: Cost100: 0.06; Cost10K: 0.04; Mistral Part No: 130014050062-R
J22 J24 J25 = 2H_Header_2x1: Cost100: 0.01; Cost10K: 0.25; Mistral Part No: M150016080001
J23 = 2C_MicroUSBAB: MfrNum: ZX62-AB-5PA(31); Mistral Part No: 150010120015-R
L9 L11 = 1M_ACM2012: MfrNum: ACM2012H-900-2P-T00; Mistral Part No: 130011090027-R
Q7-Q10 Q13-Q17 = 1Q_MOSFET_NChan_BSS138: Cost10K: 0.03; Mistral Part No: M130016080005
R547 R548 = 1R_1KOhmResistor1_16W0402: Cost100: 0.02; Cost10K: 0.02; Mistral Part No: 110009030400-R
TP22 TP23 = 2H_TestPointThroughHole: Cost100: 0.16; Cost10K: 0.1; Mistral Part No: 160016120008-R
U29 U32 = 1A_TPD4S012: MfrNum: TPD4S012DRYR; Mistral Part No: 141011080022
U31 U53 = 1A_TPS2051BD: Cost100: 1.7; MfrNum: TPS2051BDR; Mistral Part No: 142014060011-R
C236 = 1C_0.1uFCapacitor16V10%0402: Cost10K: 0.01; Loading: DNI; MfrNum: C0402C104K4RACTU; Mistral Part No: 120009030060-R
C238 = 1C_2.2uFCapacitor6.3V20%X5R0402: Cost100: 0.5; Cost10K: 0.05; Mistral Part No: 120009030281-R
J26 = 2C_Connector_USB_A: Cost100: 0.47; Cost10K: 0.47; Mistral Part No: 150009030737-P
L10 = 1L_4.7uHInductor30%3.1Asmd: Cost10K: 0.34; Mistral Part No: 130014060035-R
R393 = 1R_1.62MOhmResistor1_16W0402: Cost100: 0.01; Cost10K: 0; Mistral Part No: 110011090001
R394 = 1R_180KOhmResistor1_16W0402: Cost100: 0.01; Cost10K: 0; Mistral Part No: 110014060040-R
U30 = 1A_TPS63010YFF: Cost100: 1.7; MfrNum: TPS63010YFFR; Mistral Part No: 142014060012-R
D20 = 1E_Diode_500mA20V: Cost10K: 0.52; Mistral Part No: M130016080001
J27 = 2C_ConnectorSmartcard_52400: Mistral Part No: M150016080005
J28 J29 J58 = 2C_Conn_SIM_CCM3: Cost100: 0.81; Cost10K: 0.66; Mistral Part No: M150016080006
L25 = 1L_10uHInductor20%110mAsmd: Cost10K: 0.58; MfrNum: MLZ2012N100LT000; Mistral Part No: 130014050064-R
U34 = 1A_TCA5013: MfrNum: TCA5013ZAHR; Mistral Part No: M141016080003
C300-C303 C305-C308 = 1C_1uFCapacitor10V10%0402: Cost100: 0.33; Cost10K: 0.2; Loading: DNI; Mistral Part No: 120014050010-R
D10 D18 = 1F_LED_Red: Cost100: 0.08; Cost10K: 0.16; Mistral Part No: 130014050069-R
D11 D19 = 1F_LED_Yellow: Mistral Part No: 130015050007-R
D12 D17 = 1F_LED_Green: Cost100: 0.08; Cost10K: 0.03; Mistral Part No: 130014050065-R
D13 D16 = 1F_LED_Blue: Cost100: 0.08; Cost10K: 0.05; Mistral Part No: 130014050068-R
R486 R487 R516 R525 = 1R_150ohm1_16W1%SMD0402: Cost100: 0.01; Cost10K: 0; Mistral Part No: 110014060050-R
R488 R489 R522 R655 = 1R_82.5OhmResistor1_16W0402: Cost100: 0; Cost10K: 0.02; Mistral Part No: M110016080008
SW9-SW12 SW14-SW17 SW19-SW22 SW24-SW27 SW29-SW32 SW34-SW37 SW39-SW42 SW44-SW47 = 2W_Switch_Pushbuttonsmd: Cost100: 0.34; Cost10K: 0.33; Mistral Part No: 130014060032-R
U1 = am438x_ZDN_ePOS_EVM_13: MfrNum: XAM4384CZDNA100S; Mistral Part No: 141214060001

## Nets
AGND_ETH1: C127.2 C128.2 R186.2(P2) U8.13(AGND) U8.17(AGND)
AGNDFRAME_ETH1: J8.SHLD1 J8.SHLD2 R182.1(P1)
DGND: C101.2 C102.2 C103.2 C104.2 C106.2 C107.2 C108.2 C109.2 C110.2 C111.2 C113.2 C114.2 C115.2 C116.2 C117.2 C118.2 C125.2 C126.2 C129.2 C130.2 C131.2 C132.2 C133.2 C134.2 C135.2 C136.2 C137.2 C138.2 C141.2 C142.2 C143.2 C174.2 C175.2 C176.2 C233.2(NEG) C234.2 C235.2 C236.2 C237.2 C238.2 C239.2 C240.2 C241.2 C242.2(NEG) C243.2 C244.2 C249.2 C253.2 C254.2 C300.2 C301.2 C302.2 C303.2 C305.2 C306.2 C307.2 C308.2 C346.2 C347.2 C348.2 C349.2 C385.2 C386.2 C387.2 C388.2 C418.2 C419.2 C421.2 C422.2 C425.2 C426.2 FB7.1 FB8.1 J8.8 J11.4(GND) J11.6(GND) J11.10(GND) J11.12(GND) J11.14(GND) J11.16(GND) J11.18(GND) J11.20(GND) J23.5(GND) J24.2 J26.4(GND) J27.T5(GND) J28.C5 J29.C5 J58.C5 Q7.S(SOURCE) Q8.S(SOURCE) Q9.S(SOURCE) Q10.S(SOURCE) Q13.S(SOURCE) Q14.S(SOURCE) Q15.S(SOURCE) Q16.S(SOURCE) Q17.S(SOURCE) R111.1 R134.1(P1) R135.1 R182.2(P2) R184.2(P2) R185.1(P1) R186.1(P1) R191.1(P1) R192.1(P1) R193.1(P1) R194.1(P1) R195.1(P1) R222.2(P2) R223.2(P2) R224.2(P2) R225.2(P2) R226.2(P2) R228.2(P2) R229.2(P2) R231.2 R246.1(P1) R252.1(P1) R253.1(P1) R254.1(P1) R255.1(P1) R256.1(P1) R257.1(P1) R258.1(P1) R259.1(P1) R394.1(P1) R399.1(P1) R400.2(P2) R448.1(P1) R476.1(P1) R477.1(P1) R478.1(P1) R479.1(P1) R481.1(P1) R482.1(P1) R483.1(P1) R484.1(P1) R491.1(P1) R495.1(P1) R496.1(P1) R497.1(P1) R518.2(P2) R519.1(P1) R520.1(P1) R523.1(P1) R524.1(P1) R587.2(P2) R623.1(P1) R630.2(P2) R642.1(P1) R643.1(P1) R653.2(P2) R678.1(P1) R711.2(P2) R720.2(P2) U5.A12(VSSQ) U5.A15(VSSQ) U5.A18(VSSQ) U5.A21(VSS) U5.AA1(VSS) U5.AB7(VSSCA) U5.AB11(VSS) U5.AC5(VSS) U5.AC9(VSS) U5.AC12(VSSQ) U5.AC15(VSSQ) U5.AC18(VSSQ) U5.AC21(VSS) U5.B10(VSS) U5.C1(VSS) U5.C23(VSSQ) U5.F23(VSSQ) U5.J23(VSSQ) U5.M2(VSS) U5.M23(VSS) U5.P23(VSSQ) U5.R1(VSS) U5.U23(VSSQ) U5.V1(VSSCA) U5.Y23(VSSQ) U8.29(DGND) U8.40(IOGND) U8.TPAD(GNDPAD) U9.3(GND) U12.1(A0) U12.2(A1) U12.4(VSS) U29.4(GND) U30.B4(SYNC) U30.C1(PGND) U30.C2(PGND) U30.C3(GND) U30.D3(GND) U30.E4(GND) U31.1(GND) U32.4(GND) U34.B8(TST4) U34.B9(GNDP) U34.D2(TST3) U34.D8(GND) U34.E1(GND_UC) U34.E9(GND) U34.G2(TST2) U34.H3(GND_S) U34.H4(TST1) U34.H6(GND_S) U34.H7(GND_S) U52.2(GND) U53.1(GND) U63.3(GND) Y3.2(GND) ; also on sheet 1 2 4 5 7 8 17 18 19 20 21 22 23 24 25 26 27 28 30 31
GNDUSB0: FB7.2 J23.S1 J23.S2 J23.S3 J23.S4
GNDUSB1: FB8.2 J26.S1 J26.S2
V1_8LPDDR2: C174.1 C175.1 C176.1 C419.1 C425.1 R624.2(P2) U5.A11(VDD1) U5.A20(VDD1) U5.AB5(VDD1) U5.AC20(VDD1) U5.B3(VDD1) U5.N2(VDD1) U5.N22(VDD1) U52.5(OUT)
V1_8LPDDR2_EN: R626.2(P2) ; also on sheet 30
V3_3D: C129.1 C130.1 C133.1 C134.1 C137.1 C138.1 C141.1 C142.1 C348.1 C349.1 J11.1(VTREF) J27.SENSOR2 L25.1 R161.2(P2) R162.2(P2) R163.2(P2) R164.2(P2) R165.2(P2) R172.2(P2) R176.1(P1) R178.1(P1) R179.1(P1) R180.1(P1) R181.1(P1) R188.2(P2) R189.2(P2) R215.2(P2) R216.2(P2) R217.2(P2) R218.2(P2) R227.2(P2) R232.2(P2) R233.2(P2) R234.2(P2) R235.2(P2) R236.2(P2) R237.2(P2) R238.2(P2) R241.1(P1) R242.1(P1) R243.1(P1) R244.1(P1) R245.1(P1) R247.1(P1) R248.1(P1) R392.2(P2) R401.1(P1) R453.1(P1) R463.1(P1) R592.2(P2) R593.2(P2) R594.2(P2) R606.2(P2) R613.2(P2) R644.1(P1) R645.1(P1) R670.2(P2) R677.2(P2) U8.1(IOVDD33) U8.26(IOVDD33) U9.5(VCC) U12.8(VCC) U34.C8(VDD) U34.G8(VDD_INTF) U63.5(VCC) Y3.4(VCC) ; also on sheet 1 2 4 5 7 8 17 18 19 20 21 22 23 24 25 26 27 28 30 31
V3_3D_ETH1JCK: C125.1 C126.1 J8.3 J8.4 R164.1(P1)
V5_0D: U53.2(IN) U53.3(IN) ; also on sheet 5 30
V5_0DUSB1: C239.1 C240.1 R391.1(P1) U31.2(IN) U31.3(IN)
V5_0DUSB1_EN: R392.1(P1) U30.A4(EN)
V5_0DUSB1_REG: C238.1 R391.2(P2) R393.2(P2) U30.E1(VOUT) U30.E2(VOUT)
VBAT: C236.1 C237.1 R486.2(P2) R487.2(P2) R488.2(P2) R489.2(P2) R516.2(P2) R522.2(P2) R525.2(P2) R625.2(P2) R655.2(P2) U30.A1(VIN) U30.A2(VIN) ; also on sheet 1 2 4 5 7 19 24 28 30
VBUS0_OTG_CAP: C233.1(POS) J22.2
VBUS1_OTG_CAP: C242.1(POS) J25.2 R395.2(P2)
VCC_SC1: C249.1 C385.1 J27.T1(VCC) R403.1(P1) U34.F2(VCC_UC)
VCC_SC2: C253.1 C386.1 J28.C1 R418.1(P1) U34.H9(VCC_S1)
VCC_SC3: C254.1 C387.1 J29.C1 R423.1(P1) U34.J6(VCC_S2)
VCC_SC4: C421.1 C422.1 J58.C1 R635.1(P1) U34.J2(VCC_S3)
VDDS_DDR: C101.1 C102.1 C103.1 C104.1 C105.1 C106.1 C107.1 C108.1 C109.1 C110.1 C112.1 C113.1 C114.1 C115.1 C116.1 R230.1 U5.AA2(VDD2) U5.AA22(VDDQ) U5.AB10(VDD2) U5.AB13(VDDQ) U5.AB16(VDDQ) U5.AB19(VDDQ) U5.AB21(VDD2) U5.AC8(VDDCA) U5.B11(VDD2) U5.B13(VDDQ) U5.B16(VDDQ) U5.B19(VDDQ) U5.B21(VDD2) U5.C2(VDD2) U5.D22(VDDQ) U5.G22(VDDQ) U5.K22(VDDQ) U5.L22(VDD2) U5.R2(VDD2) U5.R22(VDDQ) U5.U2(VDDCA) U5.V22(VDDQ) U5.W2(VDDCA) ; also on sheet 18
AM438X_CLKOUT1: R298.2(P2) U1.D24(XDMA_EVENT_INTR0/CLKOUT1)
AM438X_DDR_VREF: C118.1 R133.1 R135.2 U1.T6(DDR_VREF)
AM438X_I2C_SCL2: R593.1(P1) U1.AB19(CAM0_DATA8/I2C_SCL2) U34.B5(SCL) ; also on sheet 5
AM438X_I2C_SDA2: R592.1(P1) U1.AC20(CAM0_PCLK/I2C_SDA2) U34.B6(SDA) ; also on sheet 5
AM438X_LCD_AC_BIAS_EN: R222.1(P1) SW48.20 ; also on sheet 4 5 24
AM438X_LCD_DATA0: R587.1(P1) SW48.12 ; also on sheet 4 5 24
AM438X_LCD_DATA1: R630.1(P1) SW48.13 ; also on sheet 4 5 24
AM438X_LCD_DATA2: R229.1(P1) SW48.14 ; also on sheet 4 5 24
AM438X_LCD_DATA3: R228.1(P1) SW48.15 ; also on sheet 4 5 24
AM438X_LCD_DATA4: R226.1(P1) SW48.16 ; also on sheet 4 5 24
AM438X_LCD_DATA5: R232.1(P1) ; also on sheet 4 5
AM438X_LCD_DATA6: R225.1(P1) SW48.17 ; also on sheet 4 5 24
AM438X_LCD_DATA7: R224.1(P1) SW48.18 ; also on sheet 4 5 24
AM438X_LCD_DATA8: R233.1(P1) R252.2(P2) ; also on sheet 4 5
AM438X_LCD_DATA9: R227.1(P1) R246.2(P2) ; also on sheet 4 5
AM438X_LCD_DATA10: R234.1(P1) R253.2(P2) ; also on sheet 4 5
AM438X_LCD_DATA11: R235.1(P1) R254.2(P2) ; also on sheet 4 5
AM438X_LCD_DATA12: R259.2(P2) ; also on sheet 4 5
AM438X_LCD_DATA13: R258.2(P2) ; also on sheet 4 5
AM438X_LCD_DATA14: R236.1(P1) R255.2(P2) ; also on sheet 4 5
AM438X_LCD_DATA15: R237.1(P1) R256.2(P2) ; also on sheet 4 5
AM438X_LCD_HSYNC: R223.1(P1) SW48.19 ; also on sheet 4 5 24
AM438X_LCD_VSYNC: R238.1(P1) R257.2(P2) ; also on sheet 4 5
AM438X_MDIO_CLK: R175.2(P2) U1.B17(MDIO_CLK)
AM438X_MDIO_DATA: R177.2(P2) U1.A17(MDIO_DATA)
AM438X_RMII1_CRS: R174.2(P2) U1.B14(GMII1_CRS/RMII1_CRS)
AM438X_RMII1_RXD0: R171.2(P2) U1.F17(GMII1_RXD0/RMII1_RD0)
AM438X_RMII1_RXD1: R173.2(P2) U1.B16(GMII1_RXD1/RMII1_RD1)
AM438X_RMII1_RXERR: R170.2(P2) U1.B13(GMII1_RXERR/RMII1_RXER)
AM438X_RMII1_TXD0: R166.2(P2) U1.B15(GMII1_TXD0/RMII1_TD0)
AM438X_RMII1_TXD1: R167.2(P2) U1.A14(GMII1_TXD1/RMII1_TD1)
AM438X_RMII1_TXEN: R169.2(P2) U1.A13(GMII1_TXEN/RMII1_TXEN)
AM438X_SCRD0_CLK: U1.AD18(AM438x_SCRD0_CLK) U34.D9(CLKIN_1)
AM438X_SCRD0_DATA: U1.AC18(AM438x_SCRD0_DATA) U34.E8(IOUC_1)
AM438X_SCRD1_CLK: U1.AE17(AM438x_SCRD1_CLK) U34.F9(CLKIN_2)
AM438X_SCRD1_DATA: U1.AA19(AM438x_SCRD1_DATA) U34.F8(IOUC_2)
AM438X_SCRD_IRQn: R594.1(P1) U1.AD17(CAM0_WEN/SCRD0_IRQn) U34.B3(INT)
AM438X_STATUS_LED0: R490.2(P2) R526.2(P2) ; also on sheet 28
AM438X_STATUS_LED1: R492.2(P2) R517.2(P2) ; also on sheet 23 28
AM438X_STATUS_LED2: R493.2(P2) R521.2(P2) ; also on sheet 28
AM438X_STATUS_LED3: R494.2(P2) R527.2(P2) ; also on sheet 28
AM438X_USB0_CE: TP22.1 U1.W22(USB0_CE)
AM438X_USB0_DM: L9.2 U1.W24(USB0_DM)
AM438X_USB0_DP: L9.1 U1.W25(USB0_DP)
AM438X_USB0_ID: R386.2(P2) U1.U24(USB0_ID)
AM438X_USB0_VBUS: R547.2(P2) U1.U23(USB0_VBUS)
AM438X_USB1_CE: TP23.1 U1.U22(USB1_CE)
AM438X_USB1_DM: L11.2 U1.V25(USB1_DM)
AM438X_USB1_DP: L11.1 U1.V24(USB1_DP)
AM438X_USB1_DRVVBUS: R398.2(P2) U1.F25(USB1_DRVVBUS)
AM438X_USB1_ID: R396.2(P2) U1.U25(USB1_ID)
AM438X_USB1_VBUS: R548.2(P2) U1.T25(USB1_VBUS)
DDR_A1: R87.2(P2) U1.L1(DDR_A1)
DDR_A2: R82.2(P2) U1.L2(DDR_A2)
DDR_A10: R81.2(P2) U1.M6(DDR_A10)
DDR_A13: R80.2(P2) U1.N5(DDR_A13)
DDR_BA0: R83.2(P2) U1.K1(DDR_BA0)
DDR_BA1: R84.2(P2) U1.K2(DDR_BA1)
DDR_BA2: R85.2(P2) U1.K3(DDR_BA2)
DDR_CASn: R78.2(P2) U1.N3(DDR_CASn)
DDR_CK: R73.2(P2) U1.M2(DDR_CK)
DDR_CKE0: R75.2(P2) U1.M3(DDR_CKE0)
DDR_CKE1: R296.2(P2) U1.N6(DDR_CKE1)
DDR_CKn: R74.2(P2) U1.M1(DDR_CKn)
DDR_CSN0: R86.2(P2) U1.M5(DDR_CSN0)
DDR_CSN1: R76.2(P2) U1.M4(DDR_CSN1)
DDR_D0: R88.2(P2) U1.E3(DDR_D0)
DDR_D1: R89.2(P2) U1.E2(DDR_D1)
DDR_D2: R91.2(P2) U1.E1(DDR_D2)
DDR_D3: R90.2(P2) U1.F3(DDR_D3)
DDR_D4: R92.2(P2) U1.G4(DDR_D4)
DDR_D5: R93.2(P2) U1.G3(DDR_D5)
DDR_D6: R94.2(P2) U1.G2(DDR_D6)
DDR_D7: R95.2(P2) U1.G1(DDR_D7)
DDR_D8: R96.2(P2) U1.H1(DDR_D8)
DDR_D9: R97.2(P2) U1.J6(DDR_D9)
DDR_D10: R98.2(P2) U1.J5(DDR_D10)
DDR_D11: R99.2(P2) U1.J4(DDR_D11)
DDR_D12: R100.2(P2) U1.J3(DDR_D12)
DDR_D13: R101.2(P2) U1.K6(DDR_D13)
DDR_D14: R102.2(P2) U1.K5(DDR_D14)
DDR_D15: R103.2(P2) U1.K4(DDR_D15)
DDR_D16: R104.2(P2) U1.V5(DDR_D16)
DDR_D17: R105.2(P2) U1.V4(DDR_D17)
DDR_D18: R106.2(P2) U1.V3(DDR_D18)
DDR_D19: R107.2(P2) U1.V2(DDR_D19)
DDR_D20: R108.2(P2) U1.V1(DDR_D20)
DDR_D21: R109.2(P2) U1.W4(DDR_D21)
DDR_D22: R110.2(P2) U1.W5(DDR_D22)
DDR_D23: R112.2(P2) U1.W6(DDR_D23)
DDR_D24: R113.2(P2) U1.Y2(DDR_D24)
DDR_D25: R114.2(P2) U1.Y3(DDR_D25)
DDR_D26: R115.2(P2) U1.Y4(DDR_D26)
DDR_D27: R116.2(P2) U1.AA3(DDR_D27)
DDR_D28: R117.2(P2) U1.AB2(DDR_D28)
DDR_D29: R118.2(P2) U1.AB1(DDR_D29)
DDR_D30: R119.2(P2) U1.AC1(DDR_D30)
DDR_D31: R120.2(P2) U1.AC2(DDR_D31)
DDR_DQM0: R121.2(P2) U1.F4(DDR_DQM0)
DDR_DQM1: R122.2(P2) U1.H2(DDR_DQM1)
DDR_DQM2: R123.2(P2) U1.V6(DDR_DQM2)
DDR_DQM3: R124.2(P2) U1.Y1(DDR_DQM3)
DDR_DQS0: R125.2(P2) U1.F2(DDR_DQS0)
DDR_DQS1: R127.2(P2) U1.J2(DDR_DQS1)
DDR_DQS2: R129.2(P2) U1.W1(DDR_DQS2)
DDR_DQS3: R132.2(P2) U1.AA1(DDR_DQS3)
DDR_DQSN0: R126.2(P2) U1.F1(DDR_DQS0n)
DDR_DQSN1: R128.2(P2) U1.J1(DDR_DQS1n)
DDR_DQSN2: R130.2(P2) U1.W2(DDR_DQS2n)
DDR_DQSN3: R131.2(P2) U1.AA2(DDR_DQS3n)
DDR_RASn: R77.2(P2) U1.N2(DDR_RASn)
DDR_VREF: C105.2 C111.1 C112.2 C117.1 R230.2 R231.1 U5.M22(VREF_DQ) U5.P2(VREF_CA)
DDR_WEn: R79.2(P2) U1.N4(DDR_WEn)
EMU_RSTn: C143.1 J11.15(nSRST) R217.1(P1) R221.1(P1)
ETH1_COL: R194.2(P2) U8.35(COL)
ETH1_CRS: R174.1(P1) U8.33(CRS)
ETH1_LINKLED: J8.D2 R161.1(P1) U8.22(LED_LINK/AN0)
ETH1_MDC: R175.1(P1) U8.25(MDC)
ETH1_MDIO: R163.1(P1) R177.1(P1) U8.24(MDIO)
ETH1_RESETn: U8.23(RESET_N) U9.4(Y)
ETH1_RXD0: R171.1(P1) R193.2(P2) U8.36(RXD_0)
ETH1_RXD1: R173.1(P1) R192.2(P2) U8.37(RXD_1)
ETH1_RXD2: R191.2(P2) U8.38(RXD_2)
ETH1_RXD3: R188.1(P1) U8.39(RXD_3)
ETH1_RXDV: R168.1(P1) R189.1(P1) U8.32(RX_DV)
ETH1_RXERR: R170.1(P1) R195.2(P2) U8.34(RX_ERR)
ETH1_SPEEDLED: J8.D4 R162.1(P1) U8.21(LED_SPEED/AN1)
ETH1_TXD0: R166.1(P1) U8.4(TXD_0)
ETH1_TXD1: R167.1(P1) U8.5(TXD_1)
ETH1_TXEN: R169.1(P1) U8.3(TX_EN)
ETHER1_RDN: J8.2 R178.2(P2) U8.11(RD-)
ETHER1_RDP: J8.1 R179.2(P2) U8.12(RD+)
ETHER1_TDN: J8.6 R180.2(P2) U8.14(TD-)
ETHER1_TDP: J8.5 R181.2(P2) U8.15(TD+)
GP_I2C_SCL: U12.6(SCL) ; also on sheet 2 4 7 30
GP_I2C_SDA: U12.5(SDA) ; also on sheet 2 4 7 30
GPMC_BE1n_GPIO: U1.A3(GPMC_BE1n/GPIO) ; also on sheet 2
JTAG_DBGACK: J11.19(DBGACK) TP15.1
JTAG_DBGRQ: J11.17(DBGRQ) TP14.1
JTAG_TCK: R219.2(P2) R220.2(P2) U1.AA25(JTAG_TCK) ; also on sheet 8
JTAG_TDI: J11.5(TDI) U1.Y20(JTAG_TDI) ; also on sheet 8
JTAG_TDO: R452.2(P2) U1.AA24(JTAG_TDO) ; also on sheet 8
JTAG_TMS: J11.7(TMS) R216.1(P1) U1.Y24(JTAG_TMS) ; also on sheet 8
JTAG_TRSTn: J11.3(nTRST) R218.1(P1) R448.2(P2) U1.Y25(JTAG_TRSTn) ; also on sheet 8
JTAGPOD_PRES: U63.4(Y) ; also on sheet 8
KEYPAD_PWRA: R474.1(P1) SW9.1 SW9.2 SW10.1 SW10.2 SW11.1 SW11.2 SW12.1 SW12.2 SW29.1 SW29.2 SW30.1 SW30.2 SW31.1 SW31.2 SW32.1 SW32.2
KEYPAD_PWRB: R475.1(P1) SW14.1 SW14.2 SW15.1 SW15.2 SW16.1 SW16.2 SW17.1 SW17.2 SW34.1 SW34.2 SW35.1 SW35.2 SW36.1 SW36.2 SW37.1 SW37.2
KEYPAD_PWRC: R472.1(P1) SW19.1 SW19.2 SW20.1 SW20.2 SW21.1 SW21.2 SW22.1 SW22.2 SW39.1 SW39.2 SW40.1 SW40.2 SW41.1 SW41.2 SW42.1 SW42.2
KEYPAD_PWRD: R473.1(P1) SW24.1 SW24.2 SW25.1 SW25.2 SW26.1 SW26.2 SW27.1 SW27.2 SW44.1 SW44.2 SW45.1 SW45.2 SW46.1 SW46.2 SW47.1 SW47.2
KEYPAD_SCN0: C300.1 C305.1 R476.2(P2) R481.2(P2) R535.1(P1) SW9.3 SW9.4 SW14.3 SW14.4 SW19.3 SW19.4 SW24.3 SW24.4 SW29.3 SW29.4 SW34.3 SW34.4 SW39.3 SW39.4 SW44.3 SW44.4
KEYPAD_SCN1: C301.1 C306.1 R477.2(P2) R482.2(P2) R536.1(P1) SW10.3 SW10.4 SW15.3 SW15.4 SW20.3 SW20.4 SW25.3 SW25.4 SW30.3 SW30.4 SW35.3 SW35.4 SW40.3 SW40.4 SW45.3 SW45.4
KEYPAD_SCN2: C302.1 C307.1 R478.2(P2) R483.2(P2) R537.1(P1) SW11.3 SW11.4 SW16.3 SW16.4 SW21.3 SW21.4 SW26.3 SW26.4 SW31.3 SW31.4 SW36.3 SW36.4 SW41.3 SW41.4 SW46.3 SW46.4
KEYPAD_SCN3: C303.1 C308.1 R479.2(P2) R484.2(P2) R538.1(P1) SW12.3 SW12.4 SW17.3 SW17.4 SW22.3 SW22.4 SW27.3 SW27.4 SW32.3 SW32.4 SW37.3 SW37.4 SW42.3 SW42.4 SW47.3 SW47.4
LOWPOWERn: U9.2(B) ; also on sheet 31
MEM_DDR_CA0: R77.1(P1) U5.AC6(CA0)
MEM_DDR_CA1: R78.1(P1) U5.AB6(CA1)
MEM_DDR_CA2: R79.1(P1) U5.AC7(CA2)
MEM_DDR_CA3: R80.1(P1) U5.AB8(CA3)
MEM_DDR_CA4: R81.1(P1) U5.AB9(CA4)
MEM_DDR_CA5: R87.1(P1) U5.W1(CA5)
MEM_DDR_CA6: R82.1(P1) U5.V2(CA6)
MEM_DDR_CA7: R83.1(P1) U5.U1(CA7)
MEM_DDR_CA8: R84.1(P1) U5.T2(CA8)
MEM_DDR_CA9: R85.1(P1) U5.T1(CA9)
MEM_DDR_CK: R73.1(P1) U5.Y2(CK)
MEM_DDR_CKE0: R75.1(P1) R642.2(P2) U5.AC3(CKE0)
MEM_DDR_CKE1: R296.1(P1) R643.2(P2) U5.AC4(CKE1)
MEM_DDR_CKn: R74.1(P1) U5.Y1(CKn)
MEM_DDR_CS0n: R86.1(P1) U5.AB3(CS0n)
MEM_DDR_CS1n: R76.1(P1) U5.AB4(CS1n)
MEM_DDR_D0: R88.1(P1) U5.AA23(DQ0)
MEM_DDR_D1: R89.1(P1) U5.Y22(DQ1)
MEM_DDR_D2: R91.1(P1) U5.W22(DQ2)
MEM_DDR_D3: R90.1(P1) U5.W23(DQ3)
MEM_DDR_D4: R92.1(P1) U5.V23(DQ4)
MEM_DDR_D5: R93.1(P1) U5.U22(DQ5)
MEM_DDR_D6: R94.1(P1) U5.T22(DQ6)
MEM_DDR_D7: R95.1(P1) U5.T23(DQ7)
MEM_DDR_D8: R96.1(P1) U5.H22(DQ8)
MEM_DDR_D9: R97.1(P1) U5.H23(DQ9)
MEM_DDR_D10: R98.1(P1) U5.G23(DQ10)
MEM_DDR_D11: R99.1(P1) U5.F22(DQ11)
MEM_DDR_D12: R100.1(P1) U5.E22(DQ12)
MEM_DDR_D13: R101.1(P1) U5.E23(DQ13)
MEM_DDR_D14: R102.1(P1) U5.D23(DQ14)
MEM_DDR_D15: R103.1(P1) U5.C22(DQ15)
MEM_DDR_D16: R104.1(P1) U5.AB12(DQ16)
MEM_DDR_D17: R105.1(P1) U5.AC13(DQ17)
MEM_DDR_D18: R106.1(P1) U5.AB14(DQ18)
MEM_DDR_D19: R107.1(P1) U5.AC14(DQ19)
MEM_DDR_D20: R108.1(P1) U5.AB15(DQ20)
MEM_DDR_D21: R109.1(P1) U5.AC16(DQ21)
MEM_DDR_D22: R110.1(P1) U5.AB17(DQ22)
MEM_DDR_D23: R112.1(P1) U5.AC17(DQ23)
MEM_DDR_D24: R113.1(P1) U5.B17(DQ24)
MEM_DDR_D25: R114.1(P1) U5.A17(DQ25)
MEM_DDR_D26: R115.1(P1) U5.A16(DQ26)
MEM_DDR_D27: R116.1(P1) U5.B15(DQ27)
MEM_DDR_D28: R117.1(P1) U5.B14(DQ28)
MEM_DDR_D29: R118.1(P1) U5.A14(DQ29)
MEM_DDR_D30: R119.1(P1) U5.A13(DQ30)
MEM_DDR_D31: R120.1(P1) U5.B12(DQ31)
MEM_DDR_DQM0: R121.1(P1) U5.N23(DM0)
MEM_DDR_DQM1: R122.1(P1) U5.L23(DM1)
MEM_DDR_DQM2: R123.1(P1) U5.AB20(DM2)
MEM_DDR_DQM3: R124.1(P1) U5.B20(DM3)
MEM_DDR_DQS0: R125.1(P1) U5.R23(DQS0)
MEM_DDR_DQS0n: R126.1(P1) U5.P22(DQS0n)
MEM_DDR_DQS1: R127.1(P1) U5.J22(DQS1)
MEM_DDR_DQS1n: R128.1(P1) U5.K23(DQS1n)
MEM_DDR_DQS2: R129.1(P1) U5.AB18(DQS2)
MEM_DDR_DQS2n: R130.1(P1) U5.AC19(DQS2n)
MEM_DDR_DQS3: R132.1(P1) U5.B18(DQS3)
MEM_DDR_DQS3n: R131.1(P1) U5.A19(DQS3n)
PRINTER_GPIO3: R711.1(P1) U1.AE18(CAM0_DATA0/GPIO) U34.B4(SHDN) ; also on sheet 24
RMII1_50MHZ_CLK: R183.1(P1) R298.1(P1) U1.A16(RMII1_REFCLK) U8.28(X1)
RMII1_OSC_50MHZ_CLK: R183.2(P2) Y3.3(CLK)
RTCK: J11.11(RTCK) R220.1(P1)
SAMCRD2_CLK: J28.C3 U34.J9(CLK_S1)
SAMCRD2_IO: J28.C7 U34.H8(IO_S1)
SAMCRD2_RST: J28.C2 U34.J8(RST_S1)
SAMCRD3_CLK: J29.C3 U34.J5(CLK_S2)
SAMCRD3_IO: J29.C7 U34.H5(IO_S2)
SAMCRD3_RST: J29.C2 U34.J4(RST_S2)
SAMCRD4_CLK: J58.C3 U34.J1(CLK_S3)
SAMCRD4_IO: J58.C7 U34.H2(IO_S3)
SAMCRD4_RST: J58.C2 U34.H1(RST_S3)
SMRTCRD1_C4: J27.T4(RFU0) U34.C2(C4)
SMRTCRD1_C8: J27.T8(RFU1) U34.B1(C8)
SMRTCRD1_CLK: J27.T3(CLOCK) U34.D1(CLK_UC)
SMRTCRD1_IO: J27.T7(I/O) U34.E2(IO_UC)
SMRTCRD1_PRES: J27.SENSOR1 R720.1(P1) U34.A1(PRES)
SMRTCRD1_RST: J27.T2(RESET) U34.F1(RST_UC)
SYS_RESETn: R221.2(P2) U9.1(A) ; also on sheet 2 4 26 31
TCK: J11.9(TCK) R219.1(P1)
TDO: J11.13(TDO) R452.1(P1)
USB0_CONN_DM: J23.2(DM) L9.3 U29.2(D-)
USB0_CONN_DP: J23.3(DP) L9.4 U29.1(D+)
USB0_ID: J23.4(ID) J24.1 R386.1(P1) U29.3(ID)
USB0_OVRCURn: R463.2(P2) U53.5(~{OC})
USB0_VBUS_DET: Q17.D(DRAIN) R677.1(P1) ; also on sheet 28
USB0_VBUS_EN: R388.1(P1) R518.1(P1) U53.4(EN)
USB1_CONN_DM: J26.2(DM) L11.3 U32.2(D-)
USB1_CONN_DP: J26.3(DP) L11.4 U32.1(D+)
USB1_D5V_FB: R393.1(P1) R394.2(P2) U30.E3(FB)
USB1_ID: R396.1(P1) R399.2(P2) U32.3(ID)
USB1_OVRCURn: R401.2(P2) U31.5(~{OC})
USB1_VBUS_EN: R398.1(P1) R400.1(P1) U31.4(EN)
VADD33_ETH1: C127.1 C128.1 R176.2(P2) U8.18(AVDD33)
VAM438X_DDR: R133.2 ; also on sheet 18 21
VUSB_VBUS0: C234.1 C235.1 J22.1 J23.1(VBUS) Q17.G(GATE) R547.1(P1) R678.2(P2) U29.6(VBUS) U53.6(OUT) U53.7(OUT) U53.8(OUT) ; also on sheet 30
VUSB_VBUS1: C243.1 C244.1 J25.1 J26.1(VBUS) R395.1(P1) R548.1(P1) U31.6(OUT) U31.7(OUT) U31.8(OUT) U32.6(VBUS)
N12070814: R111.2 U5.P1(ZQ)
N12532975: R134.2(P2) U1.AC3(DDR_VTP)
N13134415: J8.D3 R165.1(P1)
N13134591: J8.D1 R172.1(P1)
N13135133: C131.1 C132.1 C135.1 C136.1 U8.16(PFBIN1) U8.19(PFBOUT) U8.30(PFBIN2)
N13135261: R185.2(P2) U8.20(RBIAS)
N13797303: R472.2(P2) U1.C14(GMII1_RXD3/KEYPAD_COLC)
N13797728: R473.2(P2) U1.E16(GMII1_RXD2/KEYPAD_COLD)
N13797732: R475.2(P2) U1.D13(GMII1_RXCLK/KEYPAD_COLB)
N13828328: R184.1(P1) Y3.1(TRIn)
N13953707: J11.2(VSPLY) R453.2(P2)
N14122798: Q7.G(GATE) R490.1(P1) R491.2(P2)
N14122802: Q8.G(GATE) R492.1(P1) R495.2(P2)
N14122806: Q9.G(GATE) R493.1(P1) R496.2(P2)
N14122814: Q10.G(GATE) R494.1(P1) R497.2(P2)
N14123228: D10.1(Cathode) Q7.D(DRAIN)
N14123236: D10.2(Anode) R486.1(P1)
N14123256: D11.1(Cathode) Q8.D(DRAIN)
N14123268: D11.2(Anode) R487.1(P1)
N14123284: D12.2(Anode) R488.1(P1)
N14123288: D12.1(Cathode) Q9.D(DRAIN)
N14123296: D13.1(Cathode) Q10.D(DRAIN)
N14123312: D13.2(Anode) R489.1(P1)
N14403953: J29.C6 R423.2(P2)
N14404131: J28.C6 R418.2(P2)
N14404172: J27.T6(VPP) R403.2(P2)
N15911965: Q14.G(GATE) R519.2(P2) R526.1(P1)
N15911977: Q16.G(GATE) R517.1(P1) R520.2(P2)
N15911981: Q13.G(GATE) R521.1(P1) R523.2(P2)
N15911989: Q15.G(GATE) R524.2(P2) R527.1(P1)
N15912397: D18.1(Cathode) Q14.D(DRAIN)
N15912411: D18.2(Anode) R525.1(P1)
N15912431: D19.1(Cathode) Q16.D(DRAIN)
N15912443: D19.2(Anode) R516.1(P1)
N15912459: D17.2(Anode) R655.1(P1)
N15912463: D17.1(Cathode) Q13.D(DRAIN)
N15912471: D16.1(Cathode) Q15.D(DRAIN)
N15912487: D16.2(Anode) R522.1(P1)
N16670941: C346.1 C347.1 D20.1(CATHODE) U34.A8(VUP)
N16672336: D20.2(ANODE) L25.2 U34.A9(LX)
N17034041: R241.2(P2) SW48.1
N17034069: R242.2(P2) SW48.2
N17034107: R243.2(P2) SW48.3
N17034117: R244.2(P2) SW48.4
N17034161: R245.2(P2) SW48.5
N17194200: R538.2(P2) U1.L21(UART1_TXD/KEYPAD_ROW3)
N17194209: R537.2(P2) U1.K21(UART1_RXD/KEYPAD_ROW2)
N17194218: R536.2(P2) U1.L22(UART1_RTSN/KEYPAD_ROW1)
N17194227: R535.2(P2) U1.K22(UART1_CTSN/KEYPAD_ROW0)
N17194236: R474.2(P2) U1.D14(GMII1_TXCLK/KEYPAD_COLA)
N17638397: C388.1 U34.B7(LDO_CAP)
N18136628: R215.1(P1) U12.7(WP)
N18151232: C418.1 R625.1(P1) U52.1(IN)
N18151249: R623.2(P2) R624.1(P1) U52.4(FB)
N18151475: R626.1(P1) U52.3(EN)
N18256762: J58.C6 R635.2(P2)
N18347922: R247.2(P2) SW48.6
N18347924: R248.2(P2) SW48.7
N18348044: R645.2(P2) SW48.8
N18348046: R644.2(P2) SW48.9
N18699418: R653.1(P1) U12.3(A2)
N18817131: R388.2(P2) U1.G21(USB0_DRVVBUS)
N18818703: C426.1 J11.8(GND) R670.1(P1) U63.2(A)
N19440113: L10.1 U30.B1(L1) U30.B2(L1)
N19440133: L10.2 U30.D1(L2) U30.D2(L2)
N19440219: C241.1 U30.A3(VINA) U30.B3(VINA1) U30.C4(~{PS}) U30.D4(VSEL)
N19821379: R613.1(P1) U34.A2(GPIO4) U34.A4(GPIO3) U34.A5(GPIO2) U34.A6(GPIO1)
N20419090: R606.1(P1) U34.B2(A0)

Not connected (* = marked no-connect by the designer): J8 7 M1* M2*; J27 M1* M2* M3* M4* M5* M6*; J28 SW1* SW2*; J29 SW1* SW2*; J58 SW1* SW2*; R168 2(P2)*; SW48 10* 11*; U1 N1(DDR_A0)* P1(DDR_A4)* P2(DDR_A3)* R1(DDR_A9)* R2(DDR_A8)* R3(DDR_A7)* R4(DDR_A6)* R5(DDR_A5)* T1(DDR_RESETn)* T2(DDR_A15)* T3(DDR_A14)* T4(DDR_A12)* T5(DDR_A11)* U1(DDR_ODT0)* U2(DDR_ODT1)*; U5 A1(DNU0)* A2(DNU1)* A3(NC0)* A4(NC1)* A5(NC2)* A6(NC3)* A7(NC4)* A8(NC5)* A9(NC6)* A10(NC7)* A22(DNU2)* A23(DNU3)* AB1(DNU8)* AB2(DNU9)* AB22(DNU10)* AB23(DNU11)* AC1(DNU12)* AC2(DNU13)* AC10(NC28)* AC11(NC)* AC22(DNU14)* AC23(DNU15)* B1(DNU4)* B2(DNU5)* B4(NC8)* B5(NC)* B6(NC9)* B7(NC10)* B8(NC)* B9(NC11)* B22(DNU6)* B23(DNU7)* D1(NC12)* D2(NC13)* E1(NC14)* E2(NC15)* F1(NC16)* F2(NC)* G1(NC17)* G2(NC18)* H1(NC19)* H2(NC20)* J1(NC21)* J2(NC)* K1(NC22)* K2(NC23)* L1(NC24)* L2(NC25)* M1(NC26)* N1(NC27)*; U8 2(TX_CLK)* 6(TXD_2)* 7(TXD_3)* 8(RSV)* 9(RSV1)* 10(RSV2)* 27(X2)* 31(RX_CLK)*; U29 5(NC)*; U32 5(NC)*; U63 1(NC)

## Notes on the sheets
sheet 9
- Ethernet
- PHY ADD:0X10
sheet 10
- USB0 Port
sheet 11
- ID Memory
- ARM JTAG Connector
- AM438x Boot Configuration
sheet 12
- ARM MPU AM438X ePOS EVM
- I2C DEVICES
- ADDRESS
- I2C POWER MONITOR
- I2C0 - TPS65218
- 0100100 (24H)
- POWER RAIL
- ADDRESS
- -See the Hardware User Guide for board details
- -See the Errata Document for board issues
- I2C0 - CAT24C256W
- 1010000 (50H)
- VDD CORE
- 1000000 (40H)
- -See the PCB Build Specification for PCB Details
- I2C0 - TLV320AIC3111
- 0011000 (18H)
- VDD MPU
- 1000001 (41H)
- I2C0 - CAMERA
- 0110000 (30H)
- VAM438X_DDR
- 1000010 (42H)
- I2C0 - TOUCH CONTLR
- 1011100 (5CH)
- V1_8D_AM438X
- 1000011 (43H)
- I2C2 - TCA5013
- 0111110 (3EH)
- V3_3D_AM438X
- 1000100 (44H)
- I2C2 - SIL9022A
- 0111011 (3BH)
- VDDS_DDR
- 1000101 (45H)
sheet 13
- SmartCard Interface
- Smart Card Connector
- SAM Card 0 Connector
- SAM Card 1 Connector
- SAM Card 2 Connector
sheet 14
- Key Pad - Top Side
- Key Pad - Bottom Side
- Status LED's
  Bottom Side
- Status LED's
  Top Side
sheet 15
- USB1 Port
sheet 16
- LPDDR2 Memory
